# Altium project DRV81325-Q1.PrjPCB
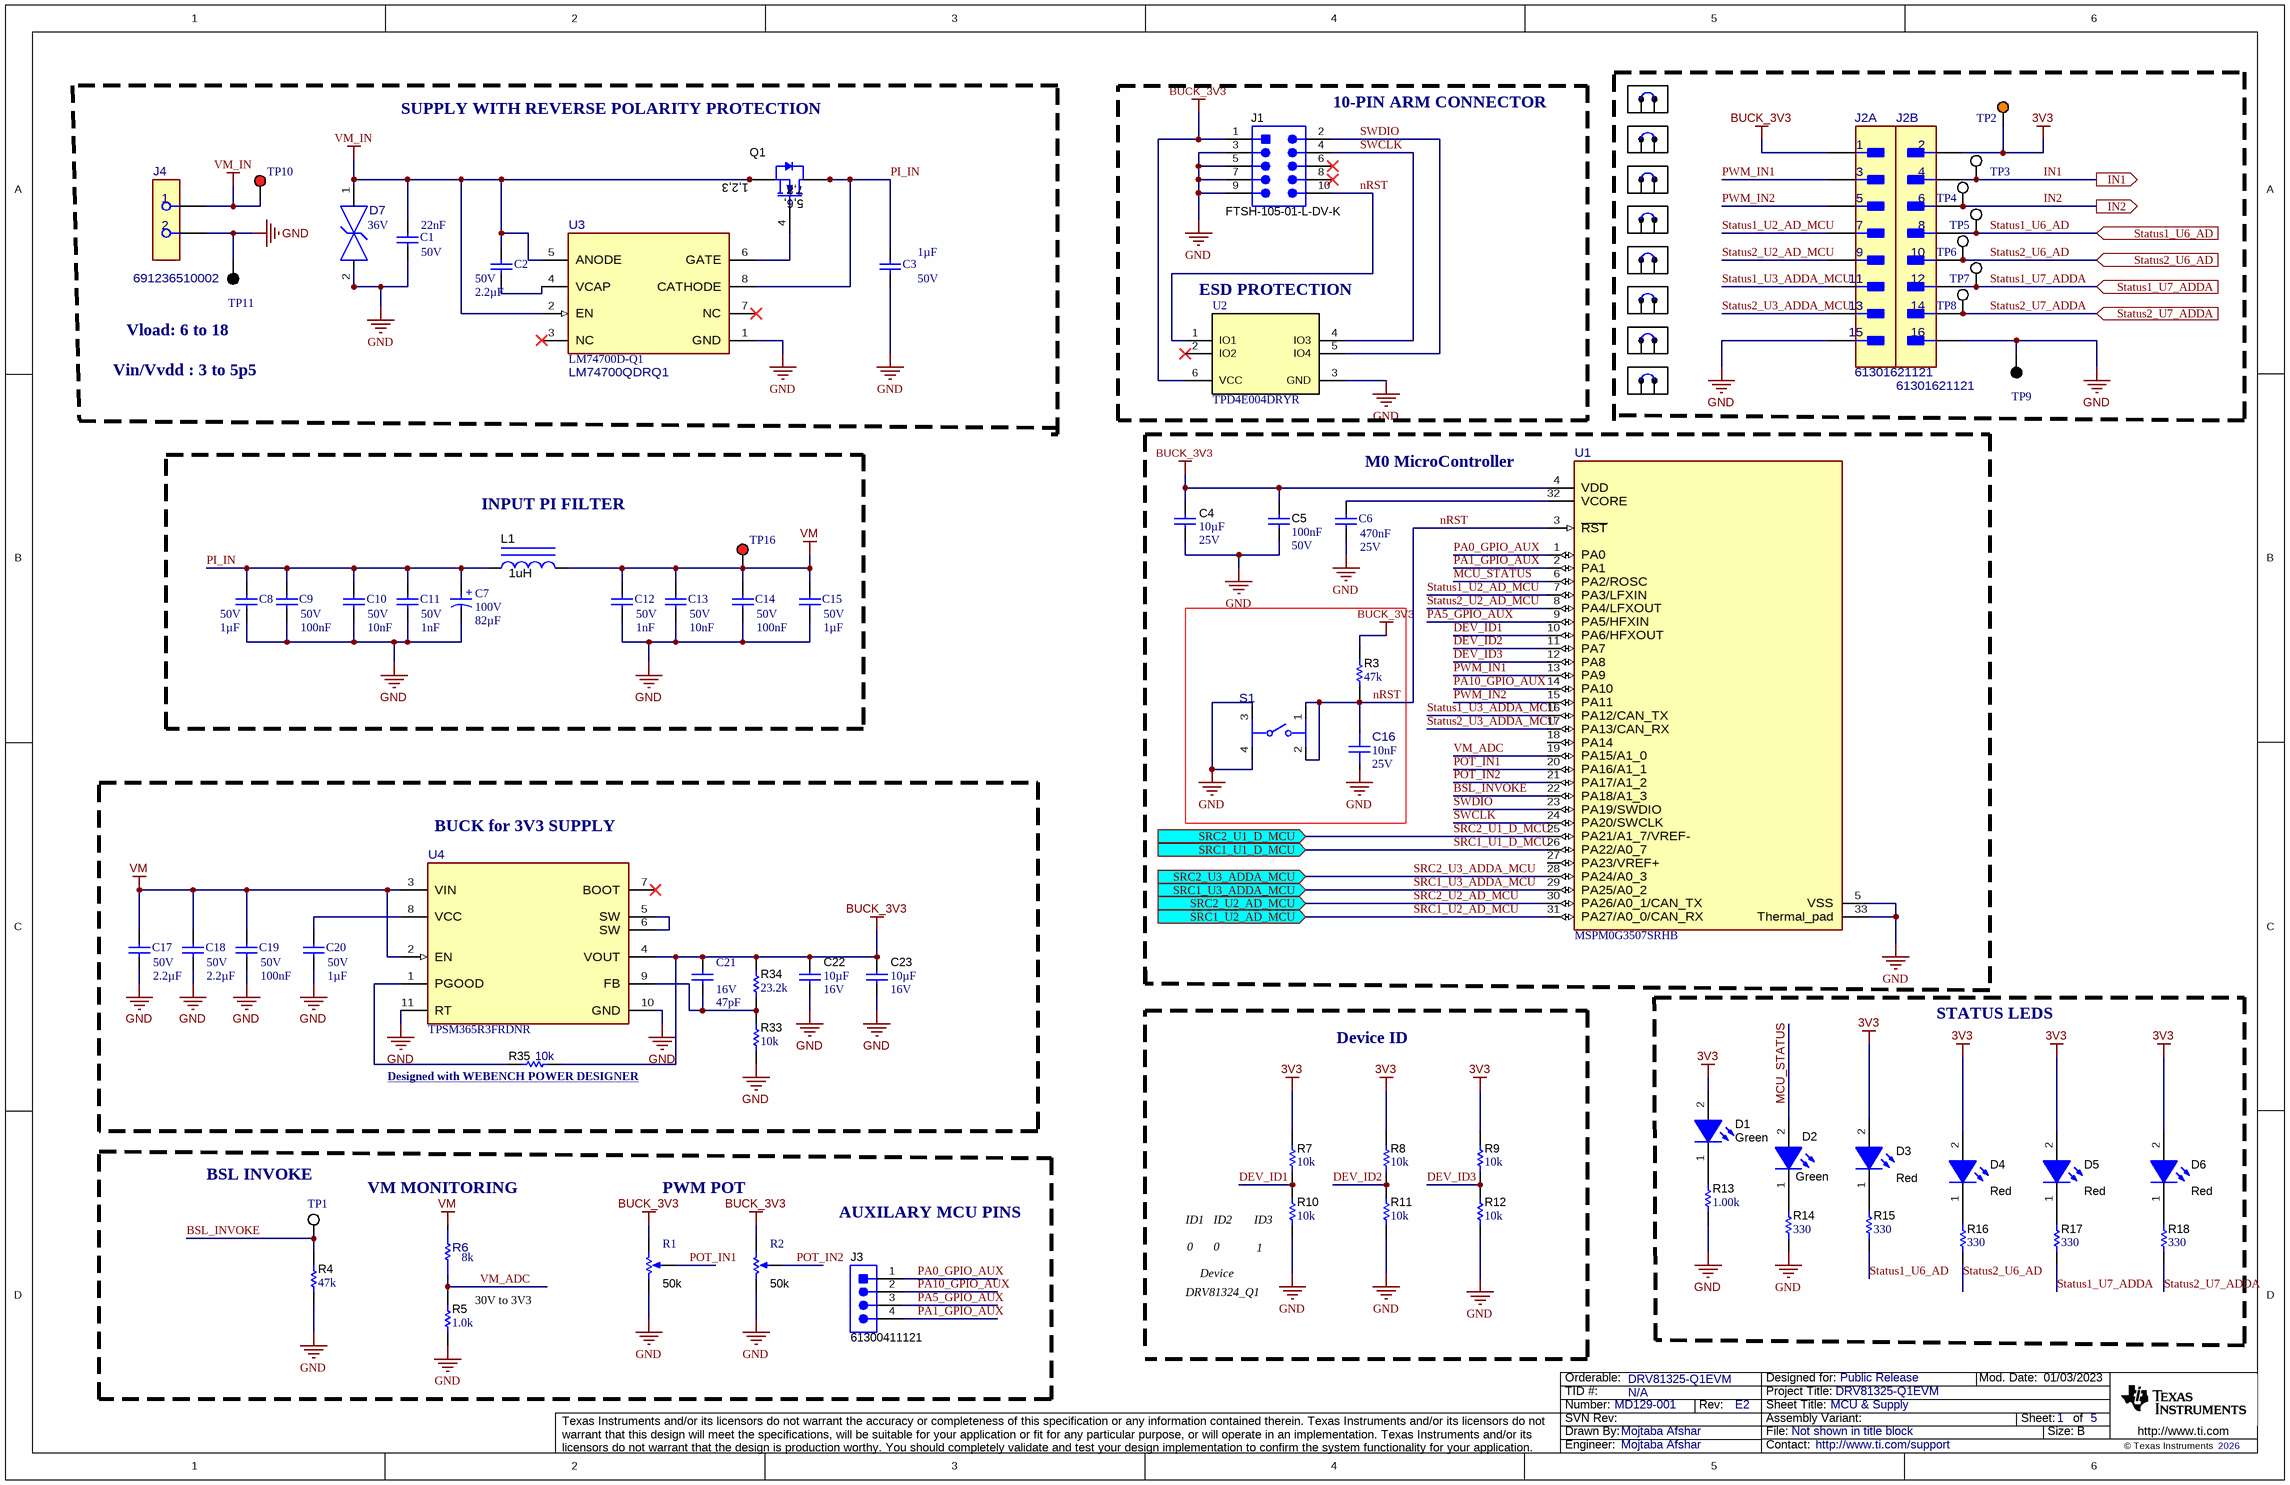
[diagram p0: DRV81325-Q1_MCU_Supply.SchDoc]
CopyrightYear: 2026; EVM_Orderable: DRV81325-Q1EVM; PCB_Layout: Mojtaba Afshar; PCB_Rev: E2; PRJ_Customer: Public Release; PRJ_Engineer: Mojtaba Afshar; PRJ_Number: MD129-001; PRJ_Title: DRV81325-Q1EVM; SCH_Rev: E2; TechSupport: http://www.ti.com/support; TID: N/A
5 sheets, 207 parts. Net scope: flat (ports and power ports of the same name join across sheets).
Board file: MD129_DRV81325_031026.PcbDoc
Sheets:
  DRV81325-Q1_MCU_Supply.SchDoc
  DRV81325-QD_IC.SchDoc
  DRV81325-QAD_IC.SchDoc
  DRV81325-QADDA_IC.SchDoc
  DRV81325-Q1_HW.SchDoc

## Sheet DRV81325-Q1_MCU_Supply.SchDoc: MCU & Supply
size 431 x 279 mm; Date: Not shown in title block; ApprovedBy: Not shown in title block; CheckedBy: Not shown in title block; Author: Not shown in title block; CompanyName: Not shown in title block; DrawnBy: Mojtaba Afshar; Engineer: Not shown in title block; Organization: Not shown in title block; Address1: Not shown in title block; Address2: Not shown in title block; Address3: Not shown in title block; Address4: Not shown in title block; DocumentNumber: 2; Revision: Use project parameter SCH_Rev; SheetNumber: 1; SheetTotal: 5; PageSetup: Record=PageOptions¦CenterHorizontal=True¦CenterVertical=True¦PrintScale=1.00¦XCorrection=1.00¦YCorrection=1.00¦PrintKind=0¦BorderSize=5000000¦LeftOffset=0¦BottomOffset=0¦Orientation=2¦PaperLength=1000¦PaperWidth=1000¦Scale=100¦PaperSource=15¦PrintQuality=600¦MediaType=1¦DitherType=10¦PaperKind=Letter¦PrintScaleMode=1

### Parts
C1  value 22nF  Rated Voltage (DC): 50V  [WCAP-CSGP_0603_L1.6W0.8H0.8_Reflow]  (hidden comment: 885012206091)
C2  value 2.2µF  Rated Voltage (DC): 50V  [WCAP-CSGP_1812_L4.5W3.2H2.5]  (hidden comment: 885012210032)
C3  value 1µF  Rated Voltage (DC): 50V  [WCAP-CSGP_1206_L3.2W1.6H1.6]  (hidden comment: 885012208093)
C4  Cap_F: 10µF  VDC_V: 25V  [0603]  (hidden comment: GRM188R61E106KA73D)
C5  Cap_F: 100nF  VDC_V: 50V  [0603]  (hidden comment: 885012206095)
C6  value 470nF  Rated Voltage (DC): 25V  [WCAP-CSGP_0603_L1.6W0.8H0.8_Reflow]  (hidden comment: 885012206075R)
C7  value 82µF  Rated Voltage (DC): 100V  [WCAP-ATUL_D10H20]  (hidden comment: 860040875004)
C8  value 1µF  Rated Voltage (DC): 50V  [WCAP-CSGP_1206_L3.2W1.6H1.6]  (hidden comment: 885012208093)
C9  value 100nF  Rated Voltage (DC): 50V  [WCAP-CSGP_0603_L1.6W0.8H0.8_Reflow]  (hidden comment: 885012206095)
C10  value 10nF  Rated Voltage (DC): 50V  [WCAP-CSGP_0402_L1W0.5H0.5]  (hidden comment: 885012205067)
C11  value 1nF  Rated Voltage (DC): 50V  [WCAP-CSGP_0402_L1W0.5H0.5]  (hidden comment: 885012205061)
C12  value 1nF  Rated Voltage (DC): 50V  [WCAP-CSGP_0402_L1W0.5H0.5]  (hidden comment: 885012205061)
C13  value 10nF  Rated Voltage (DC): 50V  [WCAP-CSGP_0402_L1W0.5H0.5]  (hidden comment: 885012205067)
C14  value 100nF  Rated Voltage (DC): 50V  [WCAP-CSGP_0603_L1.6W0.8H0.8_Reflow]  (hidden comment: 885012206095)
C15  value 1µF  Rated Voltage (DC): 50V  [WCAP-CSGP_1206_L3.2W1.6H1.6]  (hidden comment: 885012208093)
C16  Cap_F: 10nF  VDC_V: 25V  [FP-885012206065_0603-MFG]  (hidden comment: 885012206065)
C17  value 2.2µF  Rated Voltage (DC): 50V  [WCAP-CSGP_1812_L4.5W3.2H2.5]  (hidden comment: 885012210032)
C18  value 2.2µF  Rated Voltage (DC): 50V  [WCAP-CSGP_1812_L4.5W3.2H2.5]  (hidden comment: 885012210032)
C19  value 100nF  Rated Voltage (DC): 50V  [WCAP-CSGP_0603_L1.6W0.8H0.8_Reflow]  (hidden comment: 885012206095)
C20  value 1µF  Rated Voltage (DC): 50V  [WCAP-CSGP_1206_L3.2W1.6H1.6]  (hidden comment: 885012208093)
C21  value 47pF  Rated Voltage (DC): 16V  [WCAP-CSGP_0402_L1W0.5H0.5]  (hidden comment: 885012005029)
C22  VDC_V: 16V  ValueDisplayed: 10µF  [0805_150]  (hidden comment: 885012107014)
C23  VDC_V: 16V  ValueDisplayed: 10µF  [0805_150]  (hidden comment: 885012107014)
D1  value Green  [WL-SMCW_GREEN]  (hidden comment: 150060VS75000)
D2  value Green  [WL-SMCW_GREEN]  (hidden comment: 150060VS75000)
D3  value Red  [WL-SMCW_RED]  (hidden comment: 150060RS75000)
D4  value Red  [WL-SMCW_RED]  (hidden comment: 150060RS75000)
D5  value Red  [WL-SMCW_RED]  (hidden comment: 150060RS75000)
D6  value Red  [WL-SMCW_RED]  (hidden comment: 150060RS75000)
D7  VRWM: 36V  [FP-SMBJ36CA-13-F_SMB-MFG]  (hidden comment: SMBJ36CA-13-F)
J1  FTSH-105-01-L-DV-K  [Samtec_FTSH-105-01-x-DV-K]
J2  61301621121  [FP-61301621121_HDR16-MFG]  (parts A,B of 2)
J3  61300411121  [WURTH_61300411121]
J4  691236510002  [FP-691236510002_HHR2-MFG]
L1  ValueDisplayed: 1uH  [WE-HCC_1210]  (hidden comment: 7443320100)
Q1  CSD19502Q5B  [DNK0008A]  (value not drawn)
R1  value 50k  [Bourns_3352T]  (hidden comment: 3352T-1-503LF)
R2  value 50k  [Bourns_3352T]  (hidden comment: 3352T-1-503LF)
R3  ValueDisplayed: 47k  [0402]  (hidden comment: CRCW040247K0JNED)
R4  ValueDisplayed: 47k  [0402]  (hidden comment: CRCW040247K0JNED)
R5  ValueDisplayed: 1.0k  [0603]  (hidden comment: RC0603JR-071KL)
R6  value 8k  [FP-RT0603BRE078KL_0603-MFG]  (hidden comment: RT0603BRE078KL)
R7  ValueDisplayed: 10k  [0603L]  (hidden comment: RC0603JR-0710KL)
R8  ValueDisplayed: 10k  [0603L]  (hidden comment: RC0603JR-0710KL)
R9  ValueDisplayed: 10k  [0603L]  (hidden comment: RC0603JR-0710KL)
R10  ValueDisplayed: 10k  [0603L]  (hidden comment: RC0603JR-0710KL)
R11  ValueDisplayed: 10k  [0603L]  (hidden comment: RC0603JR-0710KL)
R12  ValueDisplayed: 10k  [0603L]  (hidden comment: RC0603JR-0710KL)
R13  ValueDisplayed: 1.00k  [0603]  (hidden comment: RC0603FR-071KL)
R14  ValueDisplayed: 330  [0603]  (hidden comment: RC0603JR-07330RL)
R15  ValueDisplayed: 330  [0603]  (hidden comment: RC0603JR-07330RL)
R16  ValueDisplayed: 330  [0603]  (hidden comment: RC0603JR-07330RL)
R17  ValueDisplayed: 330  [0603]  (hidden comment: RC0603JR-07330RL)
R18  ValueDisplayed: 330  [0603]  (hidden comment: RC0603JR-07330RL)
R33  ValueDisplayed: 10k  [0603L]  (hidden comment: RC0603JR-0710KL)
R34  ValueDisplayed: 23.2k  [0603]  (hidden comment: RC0603FR-0723K2L)
R35  ValueDisplayed: 10k  [0603L]  (hidden comment: RC0603JR-0710KL)
S1  430481025816  [FP-430481025816_SMT_SW_6MM2_6MM2-MFG]  (value not drawn)
SH1-J2-1  60900213421  [Wurth_60900213421]  (value not drawn)
SH2-J2  60900213421  [Wurth_60900213421]  (value not drawn)
SH3-J2  60900213421  [Wurth_60900213421]  (value not drawn)
SH4-J2  60900213421  [Wurth_60900213421]  (value not drawn)
SH5-J2  60900213421  [Wurth_60900213421]  (value not drawn)
SH6-J2  60900213421  [Wurth_60900213421]  (value not drawn)
SH7-J2  60900213421  [Wurth_60900213421]  (value not drawn)
SH8-J2  60900213421  [Wurth_60900213421]  (value not drawn)
TP1  5002  [Keystone5002]  (value not drawn)
TP2  5013  [Keystone5013]  (value not drawn)
TP3  5012  [Keystone5012]  (value not drawn)
TP4  5012  [Keystone5012]  (value not drawn)
TP5  5012  [Keystone5012]  (value not drawn)
TP6  5012  [Keystone5012]  (value not drawn)
TP7  5012  [Keystone5012]  (value not drawn)
TP8  5012  [Keystone5012]  (value not drawn)
TP9  5011  [Keystone5011]  (value not drawn)
TP10  5010  [Keystone5010]  (value not drawn)
TP11  5011  [Keystone5011]  (value not drawn)
TP16  5010  [Keystone5010]  (value not drawn)
U1  MSPM0G3507SRHB  [RHB0032E-MFG]
U2  TPD4E004DRYR  [DRY0006A]
U3  LM74700QDRQ1  PartNumber: LM74700D-Q1  [D0008A-MFG]
U4  TPSM365R3FRDNR  [RDN0011A-MFG]

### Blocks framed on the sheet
INPUT PI FILTER: C7-C15 L1 TP16
BUCK for 3V3 SUPPLY: C17-C23 R33-R35 U4
STATUS LEDS: D1-D6 R13-R18

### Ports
IN1 (out), IN2 (out), SRC1_U1_D_MCU (in), SRC1_U2_AD_MCU (in), SRC1_U3_ADDA_MCU (in), SRC2_U1_D_MCU (in), SRC2_U2_AD_MCU (in), SRC2_U3_ADDA_MCU (in), Status1_U6_AD (in), Status1_U7_ADDA (in), Status2_U6_AD (in), Status2_U7_ADDA (in)

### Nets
3V3: D1.2(A) D3.2(A) D4.2(A) D5.2(A) D6.2(A) J2.2 R7.1 R8.1 R9.1 TP2.1
BUCK_3V3: C4.1 C5.1 C21.2 C22.1 C23.1 J1.1 J2.1 R1.1(CCW) R2.1(CCW) R3.2 R34.2 R35.2 U1.4(VDD) U2.6(VCC) U4.4(VOUT)
GND: C1.1 C3.1 C4.2 C5.2 C6.1 C7.2(N) C8.1 C9.1 C10.1 C11.1 C12.1 C13.1 C14.1 C15.1 C16.2 C17.1 C18.1 C19.1 C20.1 C22.2 C23.2 D7.2 J1.3 J1.5 J1.7 J1.9 J2.15 J2.16 J4.2 R1.3(CW) R2.3(CW) R4.1 R5.1 R10.2 R11.2 R12.2 R13.1 R14.1 R33.1 S1.3 S1.4 TP9.1 TP11.1 U1.5(VSS) U1.33(Thermal_pad) U2.3(GND) U3.1(GND) U4.10(GND) U4.11(RT)
VM: C12.2 C13.2 C14.2 C15.2 C17.2 C18.2 C19.2 L1.2 R6.2 TP16.1 U4.2(EN) U4.3(VIN)
VM_IN: C1.2 C2.2 D7.1 J4.1 Q1.1(S) Q1.2(S) Q1.3(S) TP10.1 U3.2(EN) U3.5(ANODE)
BSL_INVOKE: R4.2 TP1.1 U1.22(PA18/A1_3)
DEV_ID1: R7.2 R10.1 U1.10(PA6/HFXOUT)
DEV_ID2: R8.2 R11.1 U1.11(PA7)
DEV_ID3: R9.2 R12.1 U1.12(PA8)
IN1: J2.4 TP3.1 ; port IN1
IN2: J2.6 TP4.1 ; port IN2
MCU_STATUS: D2.2(A) U1.6(PA2/ROSC)
nRST: C16.1 J1.10 R3.1 S1.1 S1.2 U1.3(~{RST}) U2.1(IO1)
PA0_GPIO_AUX: J3.1 U1.1(PA0)
PA1_GPIO_AUX: J3.4 U1.2(PA1)
PA5_GPIO_AUX: J3.3 U1.9(PA5/HFXIN)
PA10_GPIO_AUX: J3.2 U1.14(PA10)
PI_IN: C3.2 C7.1(P) C8.2 C9.2 C10.2 C11.2 L1.1 Q1.5(D) Q1.6(D) Q1.7(D) Q1.8(D) Q1.9(D) U3.8(CATHODE)
POT_IN1: R1.2(WIPER) U1.20(PA16/A1_1)
POT_IN2: R2.2(WIPER) U1.21(PA17/A1_2)
PWM_IN1: J2.3 U1.13(PA9)
PWM_IN2: J2.5 U1.15(PA11)
SRC1_U1_D_MCU: U1.26(PA22/A0_7) ; port SRC1_U1_D_MCU
SRC1_U2_AD_MCU: U1.31(PA27/A0_0/CAN_RX) ; port SRC1_U2_AD_MCU
SRC1_U3_ADDA_MCU: U1.29(PA25/A0_2) ; port SRC1_U3_ADDA_MCU
SRC2_U1_D_MCU: U1.25(PA21/A1_7/VREF-) ; port SRC2_U1_D_MCU
SRC2_U2_AD_MCU: U1.30(PA26/A0_1/CAN_TX) ; port SRC2_U2_AD_MCU
SRC2_U3_ADDA_MCU: U1.28(PA24/A0_3) ; port SRC2_U3_ADDA_MCU
Status1_U2_AD_MCU: J2.7 U1.7(PA3/LFXIN)
Status1_U3_ADDA_MCU: J2.11 U1.16(PA12/CAN_TX)
Status1_U6_AD: J2.8 R15.1 TP5.1 ; port Status1_U6_AD
Status1_U7_ADDA: J2.12 R17.1 TP7.1 ; port Status1_U7_ADDA
Status2_U2_AD_MCU: J2.9 U1.8(PA4/LFXOUT)
Status2_U3_ADDA_MCU: J2.13 U1.17(PA13/CAN_RX)
Status2_U6_AD: J2.10 R16.1 TP6.1 ; port Status2_U6_AD
Status2_U7_ADDA: J2.14 R18.1 TP8.1 ; port Status2_U7_ADDA
SWCLK: J1.4 U1.24(PA20/SWCLK) U2.4(IO3)
SWDIO: J1.2 U1.23(PA19/SWDIO) U2.5(IO4)
VM_ADC: R5.2 R6.1 U1.19(PA15/A1_0)
NetC2_1: C2.1 U3.4(VCAP)
NetC6_2: C6.2 U1.32(VCORE)
NetC20_2: C20.2 U4.8(VCC)
NetC21_1: C21.1 R33.2 R34.1 U4.9(FB)
NetD1_1: D1.1(K) R13.2
NetD2_1: D2.1(K) R14.2
NetD3_1: D3.1(K) R15.2
NetD4_1: D4.1(K) R16.2
NetD5_1: D5.1(K) R17.2
NetD6_1: D6.1(K) R18.2
NetQ1_4: Q1.4(G) U3.6(GATE)
NetR35_1: R35.1 U4.1(PGOOD)
NetU4_5: U4.5(SW) U4.6(SW)

Not connected (* = marked no-connect by the designer): J1 6* 8*; U1 18(PA14) 27(PA23/VREF+); U2 2(IO2)*; U3 3(NC)* 7(NC)*; U4 7(BOOT)*

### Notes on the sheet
- SUPPLY WITH REVERSE POLARITY PROTECTION
- (near J1) 10-PIN ARM CONNECTOR
- (near U2) ESD PROTECTION
- (near TP11) Vload: 6 to 18
- Vin/Vvdd : 3 to 5p5
- M0 MicroController
- Device ID
- (near R35) Designed with WEBENCH POWER DESIGNER <https://webench.ti.com/power-designer/switching-regulator/customize/4?VinMin=4.5&VinMax=65&O1V=3.3&O1I=0.3&base_pn=TPSM365R3F&AppType=None&Flavor=None&op_TA=30&origin=pf_panel&lang_chosen=en-US&optfactor=3&Topology=Buck&flavor=None&VoltageOption=None>
- (near TP1) BSL INVOKE
- (near R6) VM MONITORING
- PWM POT
- AUXILARY MCU PINS
- ID1
- ID2
- (near R10) ID3
- 30V to 3V3
- DRV81324_Q1
- 0
- Device
- (near R10) 1

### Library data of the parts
C1 = CMP-0119398-1: WCAP-CSGP Multilayer Ceramic Chip Capacitor, General Purpose, size 0603, X7R, 22nF, 50VDC; Manufacturer: Wurth Elektronik; Capacitance Tolerance: +/-10%; Case/Size Code: 0603; Dissipation Factor: 2.5%; Insulation Resistance: 10GOhm; Technical Reference: X7R0603223K050DFCT10000
C2 C17 C18 = CMP-0119739-1: WCAP-CSGP Multilayer Ceramic Chip Capacitor, General Purpose, size 1812, X7R, 2.2µF, 50VDC; Manufacturer: Wurth Elektronik; Capacitance Tolerance: +/-10%; Case/Size Code: 1812; Dissipation Factor: 2.5%; Insulation Resistance: 0.2GOhm; Technical Reference: X7R1812225K050DFCT10000
C3 C8 C15 C20 = CMP-0119636-1: WCAP-CSGP Multilayer Ceramic Chip Capacitor, General Purpose, size 1206, X7R, 1µF, 50VDC; Manufacturer: Wurth Elektronik; Capacitance Tolerance: +/-10%; Case/Size Code: 1206; Dissipation Factor: 3%; Insulation Resistance: 0.5GOhm; Technical Reference: X7R1206105K050DFCT10000
C4 = CMP-0860569-1: CAP, CERM, 10 µF, 25 V,+/- 10%, X5R, 0603; Manufacturer: MuRata; TaMin_C: -55°C; Polarized: N; SizeAreaWB_mm2: 4.68; U/M: EA; Value: 10uF; TaMax_C: 85°C; SizeZ_mm: 1; SizeX_mm: 1.6; SizeY_mm: 0.8; SizeArea_mm2: 1.28; AEC Category: Q200
C5 = CMP-0006837-4: CAP, CERM, 0.1 uF, 50 V, +/- 10%, X7R, 0603; Manufacturer: Wurth Elektronik; TaMin_C: -55°C; Polarized: N; SizeAreaWB_mm2: 4.68; Value1: Unknown; U/M: EA; Value: 0.1uF; TaMax_C: 125°C; SizeZ_mm: 1; SizeX_mm: 1.6; SizeY_mm: 0.8; SizeArea_mm2: 1.28; AEC Category: Q200
C6 = CMP-0119380-1: WCAP-CSGP Multilayer Ceramic Chip Capacitor, General Purpose, size 0603, X7R Class II, 470nF, 25VDC; Manufacturer: Wurth Elektronik; Capacitance Tolerance: +/-10%; Case/Size Code: 0603; Dissipation Factor: 10%; Insulation Resistance: 1.1GOhm; Technical Reference: X7R0603474K025DFCT20000
C7 = CMP-0102582-1: WCAP-ATUL Aluminum Electrolytic Capacitor, Radial, THT, D10 x H20mm, 82µF, 100V; Manufacturer: Wurth Elektronik; Capacitance Tolerance: 20%; Dissipation Factor: 9%; Endurance: 7000h; Leakage Current: 82uA; Ripple Current: 600mA; Technical Reference: ATDF200820M100DSPAAG000
C9 C14 C19 = CMP-0119402-1: WCAP-CSGP Multilayer Ceramic Chip Capacitor, General Purpose, size 0603, X7R, 100nF, 50VDC; Manufacturer: Wurth Elektronik; Capacitance Tolerance: +/-10%; Case/Size Code: 0603; Dissipation Factor: 3%; Insulation Resistance: 5GOhm; Technical Reference: X7R0603104K050DFCT10000
C10 C13 = CMP-0119297-1: WCAP-CSGP Multilayer Ceramic Chip Capacitor, General Purpose, size 0402, X7R, 10nF, 50VDC; Manufacturer: Wurth Elektronik; Capacitance Tolerance: +/-10%; Case/Size Code: 0402; Dissipation Factor: 2.5%; Insulation Resistance: 10GOhm; Technical Reference: X7R0402103K050DFCT10000
C11 C12 = CMP-0119291-1: WCAP-CSGP Multilayer Ceramic Chip Capacitor, General Purpose, size 0402, X7R, 1nF, 50VDC; Manufacturer: Wurth Elektronik; Capacitance Tolerance: +/-10%; Case/Size Code: 0402; Dissipation Factor: 2.5%; Insulation Resistance: 10GOhm; Technical Reference: X7R0402102K050DFCT10000
C16 = CMP-0120893-1: 10000 pF ±10% 25V Ceramic Capacitor X7R 0603 (1608 Metric); Manufacturer: Wurth Electronics; AEC Qualified: No; SizeZ_mm: 0.87mm; TempCo: 15%; Value: 10nF
C21 = CMP-0050226-1: WCAP-CSGP Multilayer Ceramic Chip Capacitor, General Purpose, size 0402, NP0, 47pF, 16VDC; Manufacturer: Wurth Elektronik; Capacitance Tolerance: +/-5%; Insulation Resistance: 10GOhm; Q Factor: 1000; Technical Reference: NP00402470J016DFCT10000; Case/Size Code: 0402
C22 C23 = CMP-0078154-1: CAP, CERM, 10 µF, 16 V,+/- 20%, X5R, 0805; Manufacturer: Wurth Elektronik; TaMin_C: -55°C; Polarized: N; SizeAreaWB_mm2: 6.75; U/M: EA; Value: 10uF; TaMax_C: 85°C; SizeZ_mm: 1.5; SizeX_mm: 2; SizeY_mm: 1.25; Cap_Case: 0805; SizeArea_mm2: 2.5; AEC Category: Q200
D1 D2 = CMP-0002894-2: LED, Green, SMD; Manufacturer: Wurth Elektronik; Type: AlInGaP; Value2: 2V; Io_A: 20mA; Value1: W
D3-D6 = CMP-0002947-3: LED, Red, SMD; Manufacturer: Wurth Elektronik; Value1: 0.072W; Vf_V: 2V; Angle: 140; Tjmax_C: 85°C; Type: AlInGaP; Vr_V: 5V; Io_A: 30mA; Power_TotalModule: 72mW
D7 = CMP-0098087-1: 58.1V Clamp 10.3A Ipp Tvs Diode Surface Mount SMB; Manufacturer: Diodes Inc; AEC Qualified: No; Standoff Height: 0.05mm; TJmax_C: +150°C; Direction: Bidirectional; Breakdown Voltage: 40V; SizeZ_mm: 2.5mm; Ppk: 600W; Number Of Channels: 1
J1 = CMP-0075634-2: Header(Shrouded), 1.27mm, 5x2, Gold, SMT; Manufacturer: Samtec; Pitch_mm: 1.27; Gender: Male; Cert_CSA: Y; Current_A: 3.3A; Row_Count: 2
J2 = CMP-0125672-1: Connector Header Through Hole 16 position 0.100" (2.54mm); Manufacturer: Wurth; ContactFinish: Gold; Current_A: 3A; Row_Count: 2; Voltage_V: 250V; AEC Qualified: No; Conn Gender: Male; Conn Orientation: Straight; SizeZ_mm: 8.89mm
J3 = CMP-0054798-2: Header, 2.54 mm, 4x1, Gold, TH; Manufacturer: Wurth Elektronik; Pitch_mm: 2.54; Gender: Male; Row_Count: 1; Cert_UL: Y; Shrouded: N
J4 = CMP-0121282-1: 2 Position Wire to Board Terminal Block Horizontal with Board 0.200" (5.08mm) Through Hole; Manufacturer: Wurth Electronics; Current_A: 20A; Row_Count: 1; Voltage_V: 300V; AEC Qualified: No; Conn Gender: Female; Is Female: yes; Max Wire Gauge: 12; Min Wire Gauge: 30; SizeZ_mm: 18.1mm
L1 = CMP-0063986-1: Inductor, Shielded Drum Core, Ferrite, 1 uH, 24 A, 0.0012 ohm, SMD; Manufacturer: Wurth Elektronik; Isat: 32A @ 30% inductance drop; Irms: 24A @ 50C rise; Green_Lifecycle: Active; SizeAreaWB_mm2: 188.94; DCR_ohm: 1.2m; Green_REACh: Passed; Value: 1uH; Imax_A: 24A; SizeZ_mm: 10; SizeX_mm: 12.1; SizeY_mm: 11.4; SizeArea_mm2: 137.94; Ind_H: 1µH; AEC Category: Q200
Q1 = CMP-0000915-2: MOSFET, N-CH, 80 V, 100 A, DNK0008A (VSON-CLIP-8); Alternate Manufacturer: None; Manufacturer: Texas Instruments; SizeZ_mm: 1; ChType: N; Value2: 48 nC; VdsMax_V: 80V; SizeX_mm: 6; SizeY_mm: 5; Vgs_V: 20V; Value: 80V; SizeArea_mm2: 30; AEC Category: Q101; IdsMax_A: 100A; SizeAreaWB_mm2: 56; U/M: EA; QgTyp_nC: 48
R1 R2 = CMP-0001777-2: Trimming Potentiometer, 50K, 0.5W, TH; Manufacturer: Bourns; CompType: Trimmer
R3 R4 = CMP-0026935-3: RES, 47 k, 5%, 0.063 W, AEC-Q200 Grade 0, 0402; Manufacturer: Vishay-Dale; Power_W: 63mW; TempCo: 200 ppm/C; Value_Code: 47k0; Value: 47k; EIA_Code: E24; SizeX_mm: 1; SizeY_mm: 0.5; SizeZ_mm: 0.6; Value2: 0.063W; AEC Qualified: Y; VDC_V: 50V; AEC Category: Q200; AEC Grade: 0
R5 = CMP-0025899-5: RES, 1.0 k, 5%, 0.1 W, 0603; Manufacturer: Yageo; Power_W: 100mW; TempCo: 100 ppm/C; Value_Code: 1k00; Value: 1.0k; EIA_Code: E24; Res_ohm: 1k; SizeX_mm: 1.6; SizeY_mm: 0.8; SizeZ_mm: 1; Value2: 0.1W; SizeArea_mm2: 1.28; AEC Qualified: N; VDC_V: 75V; AEC Category: Q200; SizeAreaWB_mm2: 4.68
R6 = CMP-0122747-1: 8 kOhms ±0.1% 0.1W, 1/10W Chip Resistor 0603 (1608 Metric) Thin Film; Manufacturer: Yageo; AEC Qualified: No; Power_W: 100mW; SizeZ_mm: 0.55mm; TempCo: 50ppm/°C; VDC_V: 75V
R7-R12 R33 = CMP-0025886-5: RES, 10 k, 5%, 0.1 W, 0603; Manufacturer: Yageo; Power_W: 100mW; TempCo: 100 ppm/C; Value_Code: 10k0; Value: 10k; EIA_Code: E24; SizeX_mm: 1.6; SizeY_mm: 0.8; SizeZ_mm: 1; Value2: 0.1W; SizeArea_mm2: 1.28; AEC Qualified: N; VDC_V: 75V; AEC Category: Q200; SizeAreaWB_mm2: 4.68
R13 = CMP-0022895-5: RES, 1.00 k, 1%, 0.1 W, 0603; Manufacturer: Yageo; Power_W: 100mW; TempCo: 100 ppm/C; Value_Code: 1k00; Value: 1.00k; EIA_Code: E96; Res_ohm: 1k; SizeX_mm: 1.6; SizeY_mm: 0.8; SizeZ_mm: 1; Value2: 0.1W; SizeArea_mm2: 1.28; AEC Qualified: N; VDC_V: 75V; AEC Category: Q200; SizeAreaWB_mm2: 4.68
R14-R18 = CMP-0025912-5: RES, 330, 5%, 0.1 W, 0603; Manufacturer: Yageo; Power_W: 100mW; TempCo: 100 ppm/C; Value_Code: 330R; Value: 330; EIA_Code: E24; SizeX_mm: 1.6; SizeY_mm: 0.8; SizeZ_mm: 1; Value2: 0.1W; SizeArea_mm2: 1.28; AEC Qualified: N; VDC_V: 75V; AEC Category: Q200; SizeAreaWB_mm2: 4.68
R34 = CMP-0022933-5: RES, 23.2 k, 1%, 0.1 W, 0603; Manufacturer: Yageo; Power_W: 100mW; TempCo: 100 ppm/C; Value_Code: 23k2; Value: 23.2k; EIA_Code: E96; SizeX_mm: 1.6; SizeY_mm: 0.8; SizeZ_mm: 1; Value2: 0.1W; SizeArea_mm2: 1.28; AEC Qualified: N; VDC_V: 75V; AEC Category: Q200; SizeAreaWB_mm2: 4.68
R35 = CMP-0025886-3: RES, 10 k, 5%, 0.1 W, 0603; Manufacturer: Yageo; Power_W: 100mW; TempCo: 100 ppm/C; Value_Code: 10k0; U/M: EA; Value: 10k; EIA_Code: E24; SizeX_mm: 1.6; SizeY_mm: 0.8; SizeZ_mm: 1; Value2: 0.1W; SizeArea_mm2: 1.28; VDC_V: 50V; AEC Category: Q200
S1 = CMP-0097347-1: Tactile Switch SPST-NO Top Actuated Surface Mount; Manufacturer: Wurth Electronics; VDC_V: 12V; Electromechanical Life: 1000000Cycles; SizeZ_mm: 2.7mm; Coil Resistance_ohm: 100mΩ; Operating Force: 160gf; AEC Qualified: No; Contact Current Rating: 50mA
SH1-J2-1 SH2-J2 SH3-J2 SH4-J2 SH5-J2 SH6-J2 SH7-J2 SH8-J2 = CMP-0003761-2: Shunt, 2.54mm, Gold, Black; Manufacturer: Wurth Elektronik
TP1 = CMP-0055139-2: Test Point, Miniature, White, TH; Manufacturer: Keystone Electronics; ContactFinish: Silver; Green_REACh: Passed; CT: TRUE; Green_Lifecycle: Active; CNHeader: FALSE
TP2 = CMP-0055150-1: Test Point, Multipurpose, Orange, TH; Manufacturer: Keystone; CNHeader: FALSE; Green_Lifecycle: Active; Green_REACh: Passed; ContactFinish: Silver; CT: TRUE
TP3-TP8 = CMP-0055149-2: Test Point, Multipurpose, White, TH; Manufacturer: Keystone Electronics; ContactFinish: Silver; CT: TRUE; CNHeader: FALSE; Green_Lifecycle: Active; Green_REACh: Passed
TP9 = CMP-0055148-2: Test Point, Multipurpose, Black, TH; Manufacturer: Keystone Electronics; CNHeader: FALSE; ContactFinish: Silver; Green_REACh: Passed; Green_Lifecycle: Active; CT: TRUE
TP10 TP16 = CMP-0055147-2: Test Point, Multipurpose, Red, TH; Manufacturer: Keystone Electronics; CNHeader: FALSE; Green_Lifecycle: Active; Green_REACh: Passed; ContactFinish: Silver; CT: TRUE
TP11 = CMP-0055148-2: Test Point, Multipurpose, Black, TH; Manufacturer: Keystone Electronics; CNHeader: FALSE; Green_Lifecycle: Active; Green_REACh: Passed; ContactFinish: Silver; CT: TRUE
U1 = CMP-0093963-1: Mixed-Signal Microcontrollers with CAN-FD Interface, VQFN32; Manufacturer: Texas Instruments; TaMin_C: -40°C; Interface: I2C,SPI,UART,CAN,LIN,IrDA,SMBus; Number Of Cores: 1; Number Of Pwm Channels: 16; Data Bus Width: 32bits; Frequency_Fixed: 80MHz; Core Architecture: ARM Cortex-M0+; Number Of Timers/Counters: 7; Number Of Adc Channels: 10; Number Of Uart Channels: 4; Standoff Height: 0mm; Ram Size: 32KBytes; Number Of A/D Converters: 2; SizeZ_mm: 1mm; AEC Qualified: No; TaMax_C: +125°C; Memory Size: 128KBytes; TJmax_C: +130°C; Min Supply Voltage: 1.62V; Max Supply Voltage: 3.6V; Memory Type: FLASH; Number Of I/Os: 28
U2 = CMP-0043115-2: ESD-Protection Array for High-Speed Data Interfaces, 4 Channels, -40 to +85 degC, 6-pin SON (DRY), Green (RoHS & no Sb/Br); Manufacturer: Texas Instruments; IO Leakage Current(nA): 1; USB High Speed: TRUE; IO Capacitance(Typ)(pF): 1.6; SubFamily: ESD Solution; IEC 61000-4-2 Contact(+/- kV): 8; Breakdown Voltage(Min)(V): 6; IEC 61000-4-2 Air-Gap(+/- kV): 12; AEC Category: Q200; AEC Qualified: N; CompType: IC; SizeAreaWB_mm2: 4.9; SizeArea_mm2: 1.45; SizeX_mm: 1.0; SizeZ_mm: 0.6
U3 = CMP-0125797-1: Manufacturer: Texas Instruments; SizeZ_mm: 1.75mm; Standoff Height: 0.11mm
U4 = CMP-0094617-1: 3-V to 65-V Input, 1-V to 13-V Output, 600-mA Synchronous Buck Converter Power Module in a HotRod QFN Package; Manufacturer: Texas Instruments; SizeZ_mm: 2.1mm; AEC Qualified: No; Max Duty Cycle: 98%; Max Supply Voltage: 65V; Min Supply Voltage: 3.6V; Nominal Supply Current: 17-18uA; Number Of Outputs: 1; Output Type: AdjustableProgrammable; Output Voltage: 1-13V; Standoff Height: 0mm; Switching Frequency: 200-2200kHz; TJmax_C: +125°C

## Sheet DRV81325-QD_IC.SchDoc: MSPM0G3507-Q1
size 431 x 279 mm; Date: Not shown in title block; ApprovedBy: Not shown in title block; CheckedBy: Not shown in title block; Author: Not shown in title block; CompanyName: Not shown in title block; DrawnBy: Mojtaba Afshar; Engineer: Not shown in title block; Organization: Not shown in title block; Address1: Not shown in title block; Address2: Not shown in title block; Address3: Not shown in title block; Address4: Not shown in title block; DocumentNumber: 1; Revision: Use project parameter SCH_Rev; SheetNumber: 2; SheetTotal: 5; PageSetup: Record=PageOptions¦CenterHorizontal=True¦CenterVertical=True¦PrintScale=1.00¦XCorrection=1.00¦YCorrection=1.00¦PrintKind=0¦BorderSize=5000000¦LeftOffset=0¦BottomOffset=0¦Orientation=2¦PaperLength=1000¦PaperWidth=1000¦Scale=100¦PaperSource=15¦PrintQuality=600¦MediaType=1¦DitherType=10¦PaperKind=Letter¦PrintScaleMode=1
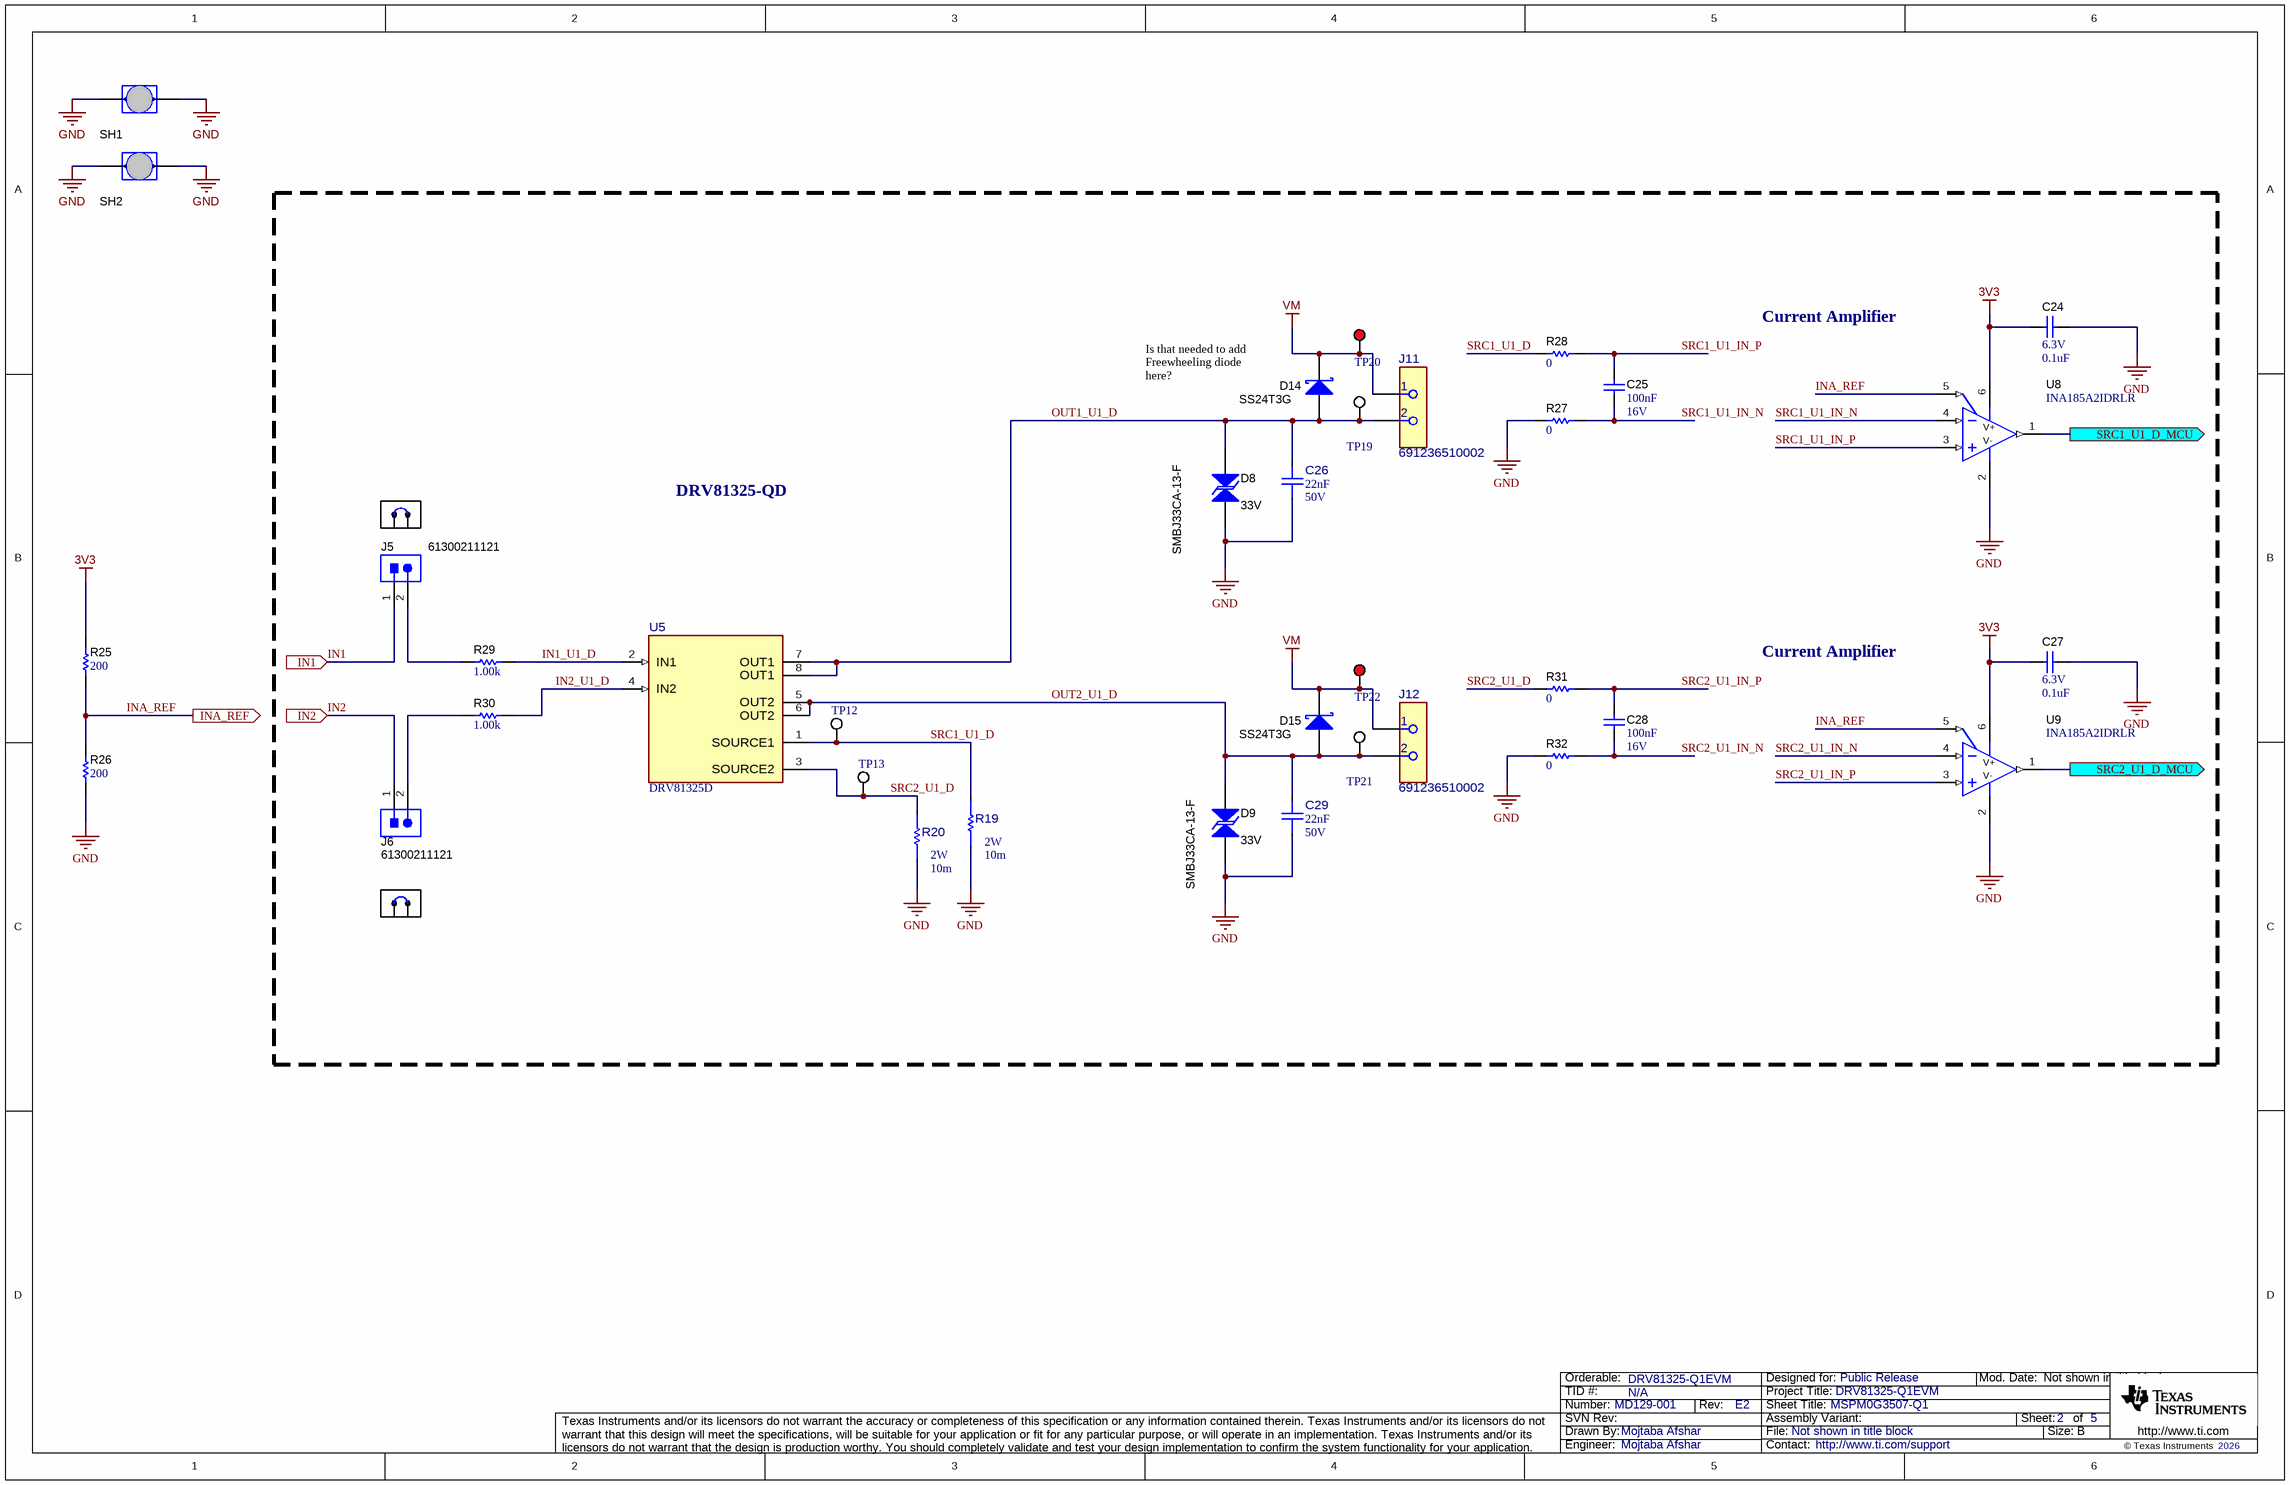
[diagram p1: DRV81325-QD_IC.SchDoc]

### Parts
C24  VDC_V: 6.3V  ValueDisplayed: 0.1uF  [0402]  (hidden comment: 885012105001)
C25  Cap_F: 100nF  VDC_V: 16V  [0603]  (hidden comment: 885012206046)
C26  Cap_F: 22nF  VDC_V: 50V  [FP-885012206091_0603-MFG]  (hidden comment: 885012206091)
C27  VDC_V: 6.3V  ValueDisplayed: 0.1uF  [0402]  (hidden comment: 885012105001)
C28  Cap_F: 100nF  VDC_V: 16V  [0603]  (hidden comment: 885012206046)
C29  Cap_F: 22nF  VDC_V: 50V  [FP-885012206091_0603-MFG]  (hidden comment: 885012206091)
D8  SMBJ33CA-13-F  value 33V  [SMB-Bi]
D9  SMBJ33CA-13-F  value 33V  [SMB-Bi]
D14  SS24T3G  [SMB]
D15  SS24T3G  [SMB]
J5  61300211121  [WURTH_61300211121]
J6  61300211121  [WURTH_61300211121]
J11  691236510002  [FP-691236510002_HHR2-MFG]
J12  691236510002  [FP-691236510002_HHR2-MFG]
R19  Res_ohm: 10m  Power_W: 2W  [FP-PCS2512DR0100ET_2512-MFG]  (hidden comment: PCS2512DR0100ET)
R20  Res_ohm: 10m  Power_W: 2W  [FP-PCS2512DR0100ET_2512-MFG]  (hidden comment: PCS2512DR0100ET)
R25  ValueDisplayed: 200  [0603]  (hidden comment: RC0603FR-07200RL)
R26  ValueDisplayed: 200  [0603]  (hidden comment: RC0603FR-07200RL)
R27  ValueDisplayed: 0  [0603]  (hidden comment: ERJ-3GEY0R00V)
R28  ValueDisplayed: 0  [0603]  (hidden comment: ERJ-3GEY0R00V)
R29  ValueDisplayed: 1.00k  [0603]  (hidden comment: RC0603FR-071KL)
R30  ValueDisplayed: 1.00k  [0603]  (hidden comment: RC0603FR-071KL)
R31  ValueDisplayed: 0  [0603]  (hidden comment: ERJ-3GEY0R00V)
R32  ValueDisplayed: 0  [0603]  (hidden comment: ERJ-3GEY0R00V)
SH1  Jumper_2p  [Harwin_D3082-05]  (value not drawn)
SH2  Jumper_2p  [Harwin_D3082-05]  (value not drawn)
SH-J5  60900213421  [Wurth_60900213421]  (value not drawn)
SH-J6  60900213421  [Wurth_60900213421]  (value not drawn)
TP12  5002  [Keystone5002]  (value not drawn)
TP13  5002  [Keystone5002]  (value not drawn)
TP19  5012  [Keystone5012]  (value not drawn)
TP20  5010  [Keystone5010]  (value not drawn)
TP21  5012  [Keystone5012]  (value not drawn)
TP22  5010  [Keystone5010]  (value not drawn)
U5  DRV81325D  [D0008A-MFG]
U8  INA185A2IDRLR  [DRL0006A]
U9  INA185A2IDRLR  [DRL0006A]

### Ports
IN1 (in), IN2 (in), INA_REF (out), SRC1_U1_D_MCU (out), SRC2_U1_D_MCU (out)

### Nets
3V3: C24.2 C27.2 R25.2 U8.6(V+) U9.6(V+)
GND: C24.1 C26.1 C27.1 C29.1 D8.1 D9.1 R19.1 R20.1 R26.1 R27.1 R32.1 SH1.1 SH1.2 SH2.1 SH2.2 U8.2(V-) U9.2(V-)
VM: D14.1(K) D15.1(K) J11.1 J12.1 TP20.1 TP22.1
IN1: J5.1 ; port IN1
IN1_U1_D: R29.2 U5.2(IN1)
IN2: J6.1 ; port IN2
IN2_U1_D: R30.2 U5.4(IN2)
INA_REF: R25.1 R26.2 U8.5(REF) U9.5(REF) ; port INA_REF
OUT1_U1_D: C26.2 D8.2 D14.2(A) J11.2 TP19.1 U5.7(OUT1) U5.8(OUT1)
OUT2_U1_D: C29.2 D9.2 D15.2(A) J12.2 TP21.1 U5.5(OUT2) U5.6(OUT2)
SRC1_U1_D: R19.2 R28.1 TP12.1 U5.1(SOURCE1)
SRC1_U1_D_MCU: U8.1(OUT) ; port SRC1_U1_D_MCU
SRC1_U1_IN_N: C25.2 R27.2 U8.4(IN-)
SRC1_U1_IN_P: C25.1 R28.2 U8.3(IN+)
SRC2_U1_D: R20.2 R31.1 TP13.1 U5.3(SOURCE2)
SRC2_U1_D_MCU: U9.1(OUT) ; port SRC2_U1_D_MCU
SRC2_U1_IN_N: C28.2 R32.2 U9.4(IN-)
SRC2_U1_IN_P: C28.1 R31.2 U9.3(IN+)
NetJ5_2: J5.2 R29.1
NetJ6_2: J6.2 R30.1

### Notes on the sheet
- Current Amplifier
- Is that needed to add Freewheeling diode here?
- DRV81325-QD

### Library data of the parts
C24 C27 = CMP-0006219-2: CAP, CERM, 0.1 uF, 6.3 V, +/- 20%, X5R, 0402; Manufacturer: Wurth Elektronik; TaMin_C: -55°C; Polarized: N; SizeAreaWB_mm2: 3; Value1: Unknown; U/M: EA; Value: 0.1uF; TaMax_C: 85°C; SizeZ_mm: 0.6; SizeX_mm: 1; SizeY_mm: 0.5; Cap_F: 100nF; AEC Category: Q200
C25 C28 = CMP-0006829-4: CAP, CERM, 0.1 uF, 16 V, +/- 10%, X7R, 0603; Manufacturer: Wurth Elektronik; TaMin_C: -55°C; Polarized: N; SizeAreaWB_mm2: 4.68; Value1: Unknown; U/M: EA; Value: 0.1uF; TaMax_C: 125°C; SizeZ_mm: 1; SizeX_mm: 1.6; SizeY_mm: 0.8; SizeArea_mm2: 1.28; AEC Category: Q200
C26 C29 = CMP-0120895-1: 0.022 µF ±10% 50V Ceramic Capacitor X7R 0603 (1608 Metric); Manufacturer: Wurth Electronics; AEC Qualified: No; SizeZ_mm: 0.87mm; TempCo: 15%; Value: 22nF
D8 D9 = CMP-0005564-3: Diode, TVS, Bi, 33 V, SMB; Manufacturer: Diodes Inc.; SizeX_mm: 5.6; Ppk: 600W; SizeAreaWB_mm2: 44.156; SizeZ_mm: 2.6; SizeArea_mm2: 21.336; SizeY_mm: 3.81; AEC Category: Q101
D14 D15 = CMP-0028778-2: Diode, Schottky, 40 V, 2 A, AEC-Q101, SMB; Manufacturer: ON Semiconductor; AEC Qualified: Y; Value: 40V; TJmax_C: 150°C; Value1: 2A; Green_Lifecycle: Active; Value2: 0.5V; SizeX_mm: 5.6; SizeAreaWB_mm2: 44.156; SizeY_mm: 3.81; SizeArea_mm2: 21.336; Green_REACh: Passed; SizeZ_mm: 2.6; AEC Category: Q101; Vf_V: 500mV
J5 J6 = CMP-0054794-2: Header, 2.54 mm, 2x1, Gold, TH; Manufacturer: Wurth Elektronik; Shrouded: N; Gender: Male; Green_REACh: Passed; Pitch_mm: 2.54; Green_Lifecycle: Active; Row_Count: 1; Cert_UL: Y
J11 J12 = CMP-0121282-1: as J4 on sheet DRV81325-Q1_MCU_Supply
R19 R20 = CMP-0088493-1: 10 mOhms ±0.5% 2W Chip Resistor 2512 (6432 Metric) Automotive AEC-Q200, Current Sense, Moisture Resistant Metal Film; Manufacturer: Ohmite; SizeZ_mm: 0.664mm; AEC Grade: Grade 0; TempCo: 50ppm/°C; AEC Qualified: Yes; Tolerance_%: 0%
R25 R26 = CMP-0022902-5: RES, 200, 1%, 0.1 W, 0603; Manufacturer: Yageo; Power_W: 100mW; TempCo: 100 ppm/C; Value_Code: 200R; Value: 200; EIA_Code: E96; SizeX_mm: 1.6; SizeY_mm: 0.8; SizeZ_mm: 1; Value2: 0.1W; SizeArea_mm2: 1.28; AEC Qualified: N; VDC_V: 75V; AEC Category: Q200; SizeAreaWB_mm2: 4.68
R27 R28 R31 R32 = CMP-0025874-4: RES, 0, 5%, 0.1 W, AEC-Q200 Grade 0, 0603; Manufacturer: Panasonic; Power_W: 100mW; TempCo: 600 ppm/C; Value_Code: 0000; Value: 0; EIA_Code: E24; SizeX_mm: 1.6; SizeY_mm: 0.8; SizeZ_mm: 1; Value2: 0.1W; SizeArea_mm2: 1.28; AEC Qualified: Y; VDC_V: 50V; AEC Category: Q200; SizeAreaWB_mm2: 4.68
R29 R30 = CMP-0022895-5: as R13 on sheet DRV81325-Q1_MCU_Supply
SH1 SH2 = CMP-0075110-1: 1mm Uninsulated Shorting Plug, 10.16mm spacing, TH; PartNumber: D3082-05; Manufacturer: Harwin; CNHeader: False; CompType: Jumper Wire; Green_Lifecycle: Active; Green_REACh: Passed
SH-J5 SH-J6 = CMP-0003761-2: as SH1-J2-1 on sheet DRV81325-Q1_MCU_Supply
TP12 TP13 = CMP-0055139-2: as TP1 on sheet DRV81325-Q1_MCU_Supply
TP19 TP21 = CMP-0055149-2: as TP3 on sheet DRV81325-Q1_MCU_Supply
TP20 TP22 = CMP-0055147-2: Test Point, Multipurpose, Red, TH; Manufacturer: Keystone Electronics; CT: TRUE; ContactFinish: Silver; Green_Lifecycle: Active; CNHeader: FALSE; Green_REACh: Passed
U5 = CMP-0127644-1: Dual Channel Protected Low side switch, SOIC8; Manufacturer: Texas Instruments; SizeZ_mm: 1.75mm; AEC Qualified: Yes; AEC Grade: Grade 1; Max Supply Voltage: 5.5V; Min Supply Voltage: 3V; Number Of Outputs: 2; Standoff Height: 0.11mm; TaMax_C: +125°C; TaMin_C: -40°C; TJmax_C: +150°C
U8 U9 = CMP-0085242-1: Bidirectional, Precision Low- and High-Side Voltage Output, Current-Sense Amplifier, DRL0006A (SOT-5X3-6); Alternate PartNumber: INA185A2IDRLT; Alternate Manufacturer: Texas Instruments; SizeY_mm: 1.6; SizeAreaWB_mm2: 6.76; AEC Category: Q200; SizeArea_mm2: 2.56; CompType: IC; AEC Qualified: N; SizeZ_mm: 0.6

## Sheet DRV81325-QAD_IC.SchDoc
size 431 x 279 mm; Date: Not shown in title block; ApprovedBy: Not shown in title block; CheckedBy: Not shown in title block; Author: Not shown in title block; CompanyName: Not shown in title block; Engineer: Not shown in title block; Organization: Not shown in title block; Address1: Not shown in title block; Address2: Not shown in title block; Address3: Not shown in title block; Address4: Not shown in title block; DocumentNumber: 1; Revision: Use project parameter SCH_Rev; SheetNumber: 3; SheetTotal: 5; PageSetup: Record=PageOptions¦CenterHorizontal=True¦CenterVertical=True¦PrintScale=1.00¦XCorrection=1.00¦YCorrection=1.00¦PrintKind=0¦BorderSize=5000000¦LeftOffset=0¦BottomOffset=0¦Orientation=2¦PaperLength=1000¦PaperWidth=1000¦Scale=100¦PaperSource=15¦PrintQuality=600¦MediaType=1¦DitherType=10¦PaperKind=Letter¦PrintScaleMode=1
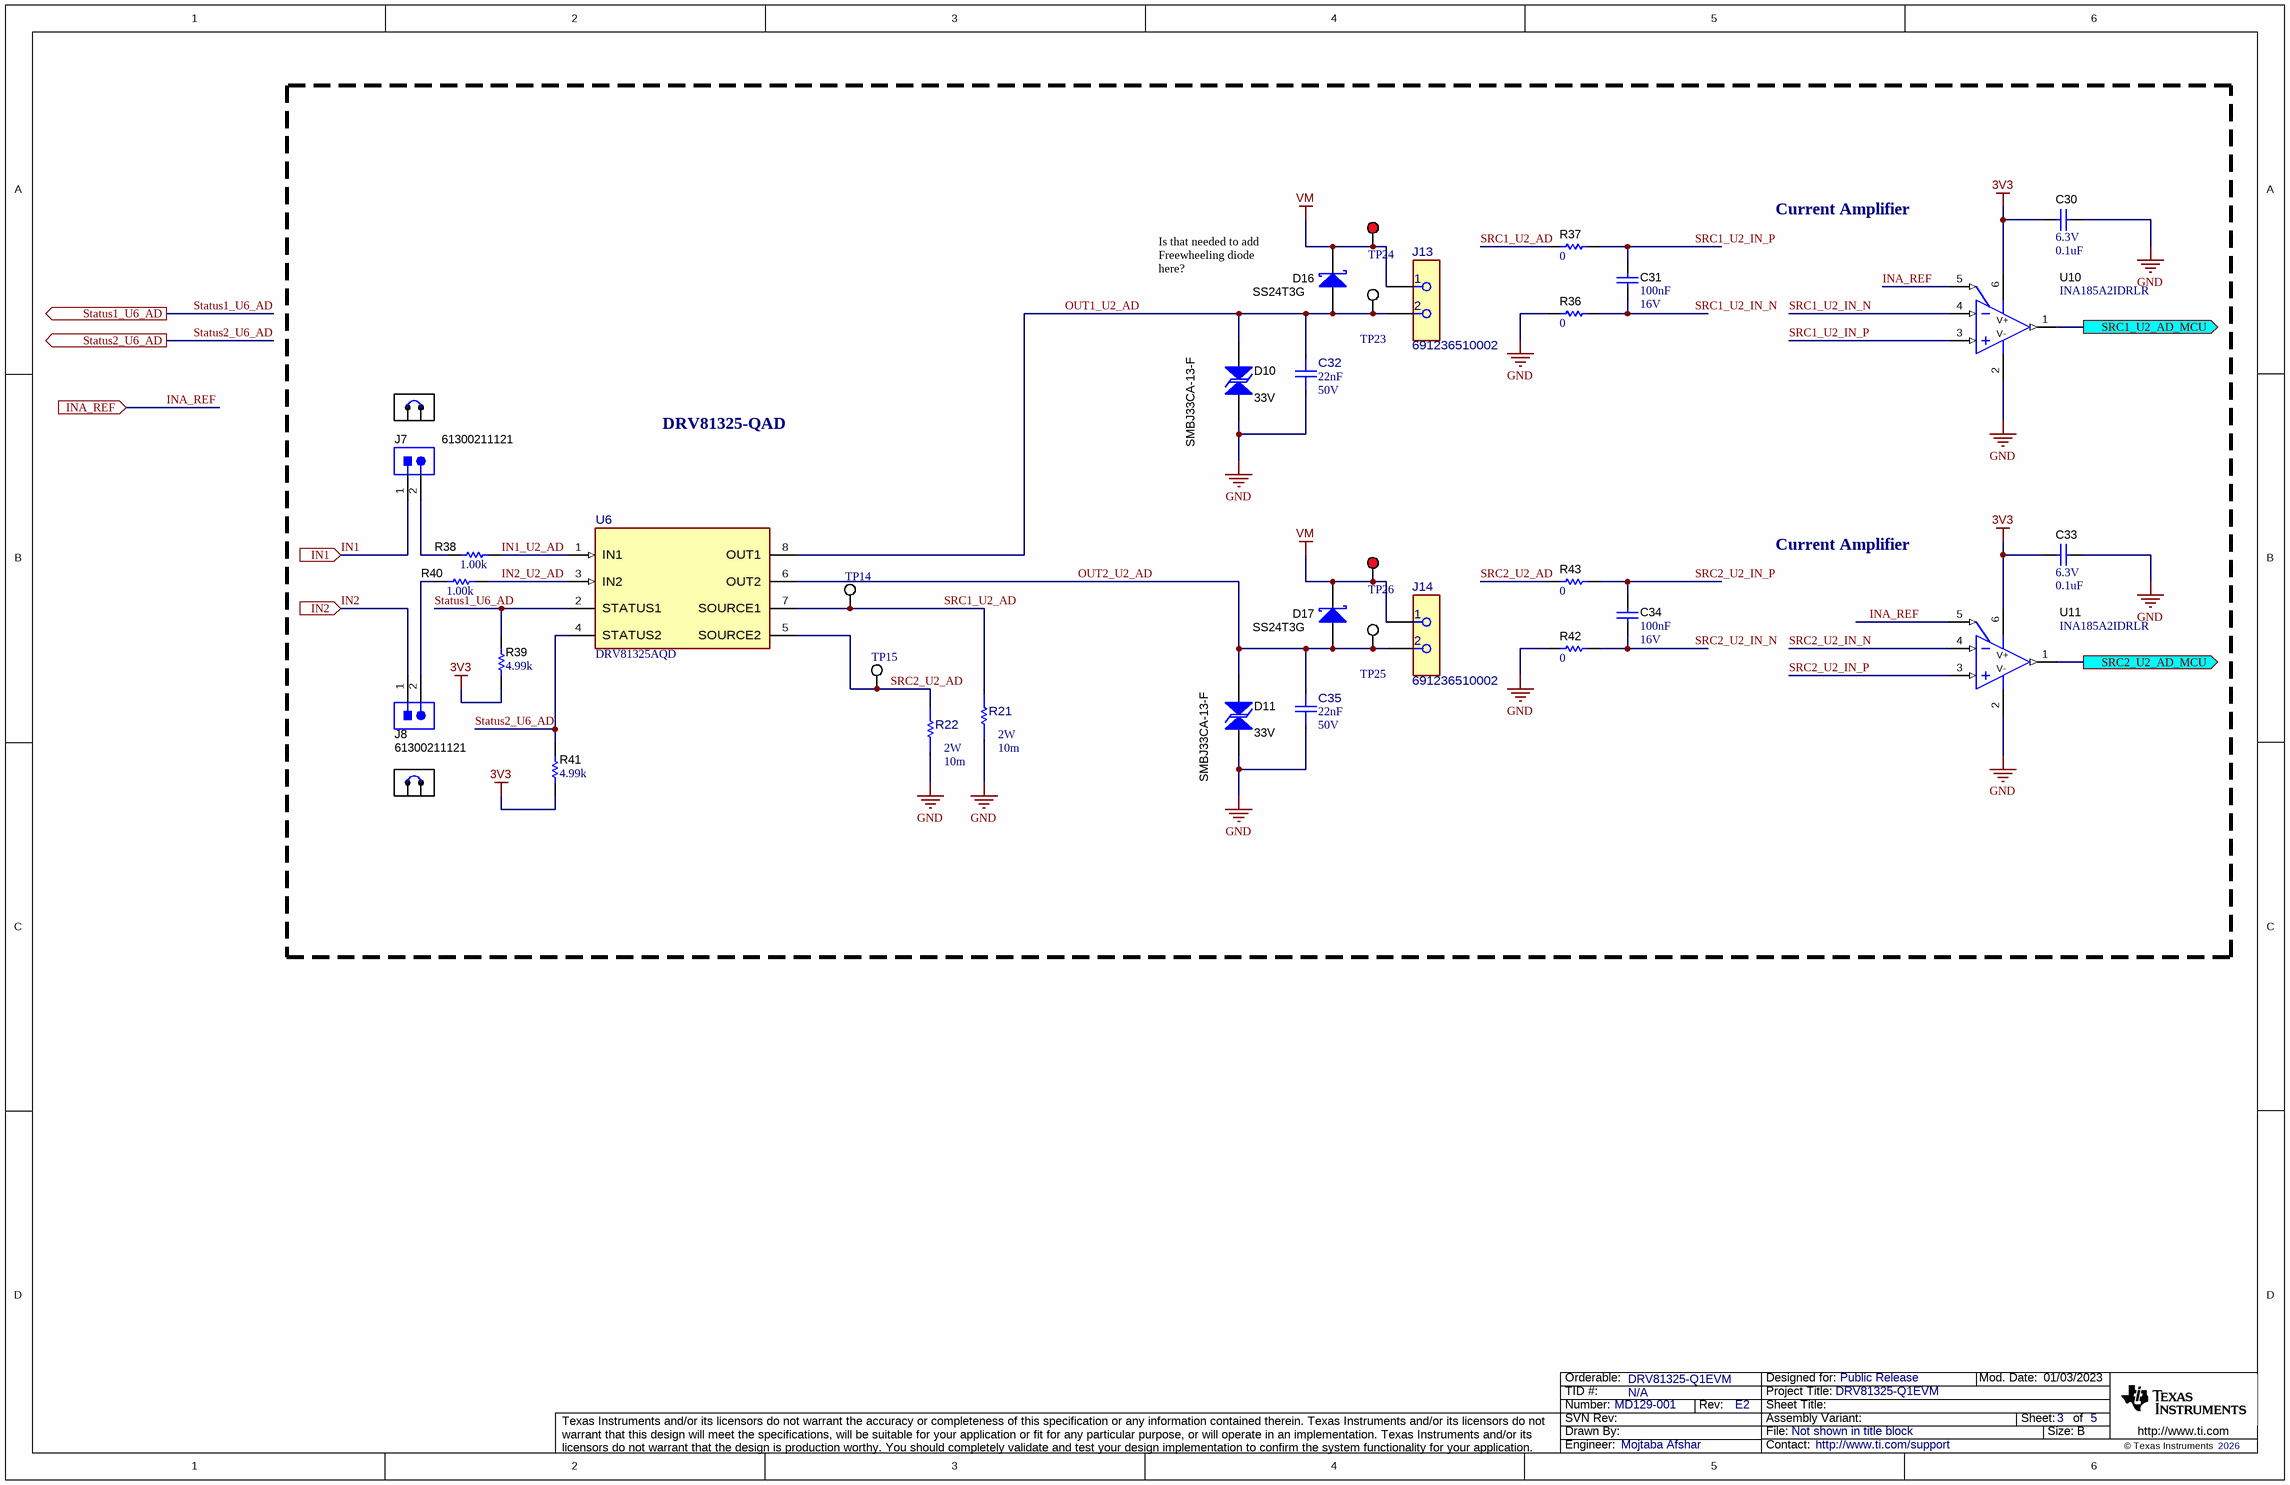
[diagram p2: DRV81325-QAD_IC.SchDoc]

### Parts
C30  VDC_V: 6.3V  ValueDisplayed: 0.1uF  [0402]  (hidden comment: 885012105001)
C31  Cap_F: 100nF  VDC_V: 16V  [0603]  (hidden comment: 885012206046)
C32  Cap_F: 22nF  VDC_V: 50V  [FP-885012206091_0603-MFG]  (hidden comment: 885012206091)
C33  VDC_V: 6.3V  ValueDisplayed: 0.1uF  [0402]  (hidden comment: 885012105001)
C34  Cap_F: 100nF  VDC_V: 16V  [0603]  (hidden comment: 885012206046)
C35  Cap_F: 22nF  VDC_V: 50V  [FP-885012206091_0603-MFG]  (hidden comment: 885012206091)
D10  SMBJ33CA-13-F  value 33V  [SMB-Bi]
D11  SMBJ33CA-13-F  value 33V  [SMB-Bi]
D16  SS24T3G  [SMB]
D17  SS24T3G  [SMB]
J7  61300211121  [WURTH_61300211121]
J8  61300211121  [WURTH_61300211121]
J13  691236510002  [FP-691236510002_HHR2-MFG]
J14  691236510002  [FP-691236510002_HHR2-MFG]
R21  Res_ohm: 10m  Power_W: 2W  [FP-PCS2512DR0100ET_2512-MFG]  (hidden comment: PCS2512DR0100ET)
R22  Res_ohm: 10m  Power_W: 2W  [FP-PCS2512DR0100ET_2512-MFG]  (hidden comment: PCS2512DR0100ET)
R36  ValueDisplayed: 0  [0603]  (hidden comment: ERJ-3GEY0R00V)
R37  ValueDisplayed: 0  [0603]  (hidden comment: ERJ-3GEY0R00V)
R38  ValueDisplayed: 1.00k  [0603]  (hidden comment: RC0603FR-071KL)
R39  ValueDisplayed: 4.99k  [0603]  (hidden comment: RC0603FR-074K99L)
R40  ValueDisplayed: 1.00k  [0603]  (hidden comment: RC0603FR-071KL)
R41  ValueDisplayed: 4.99k  [0603]  (hidden comment: RC0603FR-074K99L)
R42  ValueDisplayed: 0  [0603]  (hidden comment: ERJ-3GEY0R00V)
R43  ValueDisplayed: 0  [0603]  (hidden comment: ERJ-3GEY0R00V)
SH-J7  60900213421  [Wurth_60900213421]  (value not drawn)
SH-J8  60900213421  [Wurth_60900213421]  (value not drawn)
TP14  5002  [Keystone5002]  (value not drawn)
TP15  5002  [Keystone5002]  (value not drawn)
TP23  5012  [Keystone5012]  (value not drawn)
TP24  5010  [Keystone5010]  (value not drawn)
TP25  5012  [Keystone5012]  (value not drawn)
TP26  5010  [Keystone5010]  (value not drawn)
U6  DRV81325AQD  [D0008A-MFG]
U10  INA185A2IDRLR  [DRL0006A]
U11  INA185A2IDRLR  [DRL0006A]

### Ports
IN1 (in), IN2 (in), INA_REF (in), SRC1_U2_AD_MCU (out), SRC2_U2_AD_MCU (out), Status1_U6_AD (out), Status2_U6_AD (out)

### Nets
3V3: C30.2 C33.2 R39.1 R41.1 U10.6(V+) U11.6(V+)
GND: C30.1 C32.1 C33.1 C35.1 D10.1 D11.1 R21.1 R22.1 R36.1 R42.1 U10.2(V-) U11.2(V-)
VM: D16.1(K) D17.1(K) J13.1 J14.1 TP24.1 TP26.1
IN1: J7.1 ; port IN1
IN1_U2_AD: R38.2 U6.1(IN1)
IN2: J8.1 ; port IN2
IN2_U2_AD: R40.2 U6.3(IN2)
INA_REF: U10.5(REF) U11.5(REF) ; port INA_REF
OUT1_U2_AD: C32.2 D10.2 D16.2(A) J13.2 TP23.1 U6.8(OUT1)
OUT2_U2_AD: C35.2 D11.2 D17.2(A) J14.2 TP25.1 U6.6(OUT2)
SRC1_U2_AD: R21.2 R37.1 TP14.1 U6.7(SOURCE1)
SRC1_U2_AD_MCU: U10.1(OUT) ; port SRC1_U2_AD_MCU
SRC1_U2_IN_N: C31.2 R36.2 U10.4(IN-)
SRC1_U2_IN_P: C31.1 R37.2 U10.3(IN+)
SRC2_U2_AD: R22.2 R43.1 TP15.1 U6.5(SOURCE2)
SRC2_U2_AD_MCU: U11.1(OUT) ; port SRC2_U2_AD_MCU
SRC2_U2_IN_N: C34.2 R42.2 U11.4(IN-)
SRC2_U2_IN_P: C34.1 R43.2 U11.3(IN+)
Status1_U6_AD: R39.2 U6.2(STATUS1) ; port Status1_U6_AD
Status2_U6_AD: R41.2 U6.4(STATUS2) ; port Status2_U6_AD
NetJ7_2: J7.2 R38.1
NetJ8_2: J8.2 R40.1

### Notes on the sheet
- Current Amplifier
- Is that needed to add Freewheeling diode here?
- DRV81325-QAD

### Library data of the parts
C30 C33 = CMP-0006219-2: as C24 on sheet DRV81325-QD_IC
C31 C34 = CMP-0006829-4: as C25 on sheet DRV81325-QD_IC
C32 C35 = CMP-0120895-1: as C26 on sheet DRV81325-QD_IC
D10 D11 = CMP-0005564-3: as D8 on sheet DRV81325-QD_IC
D16 D17 = CMP-0028778-2: as D14 on sheet DRV81325-QD_IC
J7 J8 = CMP-0054794-2: as J5 on sheet DRV81325-QD_IC
J13 J14 = CMP-0121282-1: as J4 on sheet DRV81325-Q1_MCU_Supply
R21 R22 = CMP-0088493-1: as R19 on sheet DRV81325-QD_IC
R36 R37 R42 R43 = CMP-0025874-4: as R27 on sheet DRV81325-QD_IC
R38 R40 = CMP-0022895-5: as R13 on sheet DRV81325-Q1_MCU_Supply
R39 R41 = CMP-0023155-5: RES, 4.99 k, 1%, 0.1 W, 0603; Manufacturer: Yageo; Power_W: 100mW; TempCo: 100 ppm/C; Value_Code: 4k99; Value: 4.99k; EIA_Code: E96; SizeX_mm: 1.6; SizeY_mm: 0.8; SizeZ_mm: 1; Value2: 0.1W; SizeArea_mm2: 1.28; AEC Qualified: N; VDC_V: 75V; AEC Category: Q200; SizeAreaWB_mm2: 4.68
SH-J7 SH-J8 = CMP-0003761-2: as SH1-J2-1 on sheet DRV81325-Q1_MCU_Supply
TP14 TP15 = CMP-0055139-2: as TP1 on sheet DRV81325-Q1_MCU_Supply
TP23 TP25 = CMP-0055149-2: as TP3 on sheet DRV81325-Q1_MCU_Supply
TP24 TP26 = CMP-0055147-2: as TP20 on sheet DRV81325-QD_IC
U6 = CMP-0127803-1: Manufacturer: Texas Instruments; SizeZ_mm: 1.75mm; Standoff Height: 0.11mm
U10 U11 = CMP-0085242-1: as U8 on sheet DRV81325-QD_IC

## Sheet DRV81325-QADDA_IC.SchDoc
size 431 x 279 mm; Date: Not shown in title block; ApprovedBy: Not shown in title block; CheckedBy: Not shown in title block; Author: Not shown in title block; CompanyName: Not shown in title block; Engineer: Not shown in title block; Organization: Not shown in title block; Address1: Not shown in title block; Address2: Not shown in title block; Address3: Not shown in title block; Address4: Not shown in title block; DocumentNumber: 1; Revision: Use project parameter SCH_Rev; SheetNumber: 4; SheetTotal: 5; PageSetup: Record=PageOptions¦CenterHorizontal=True¦CenterVertical=True¦PrintScale=1.00¦XCorrection=1.00¦YCorrection=1.00¦PrintKind=0¦BorderSize=5000000¦LeftOffset=0¦BottomOffset=0¦Orientation=2¦PaperLength=1000¦PaperWidth=1000¦Scale=100¦PaperSource=15¦PrintQuality=600¦MediaType=1¦DitherType=10¦PaperKind=Letter¦PrintScaleMode=1
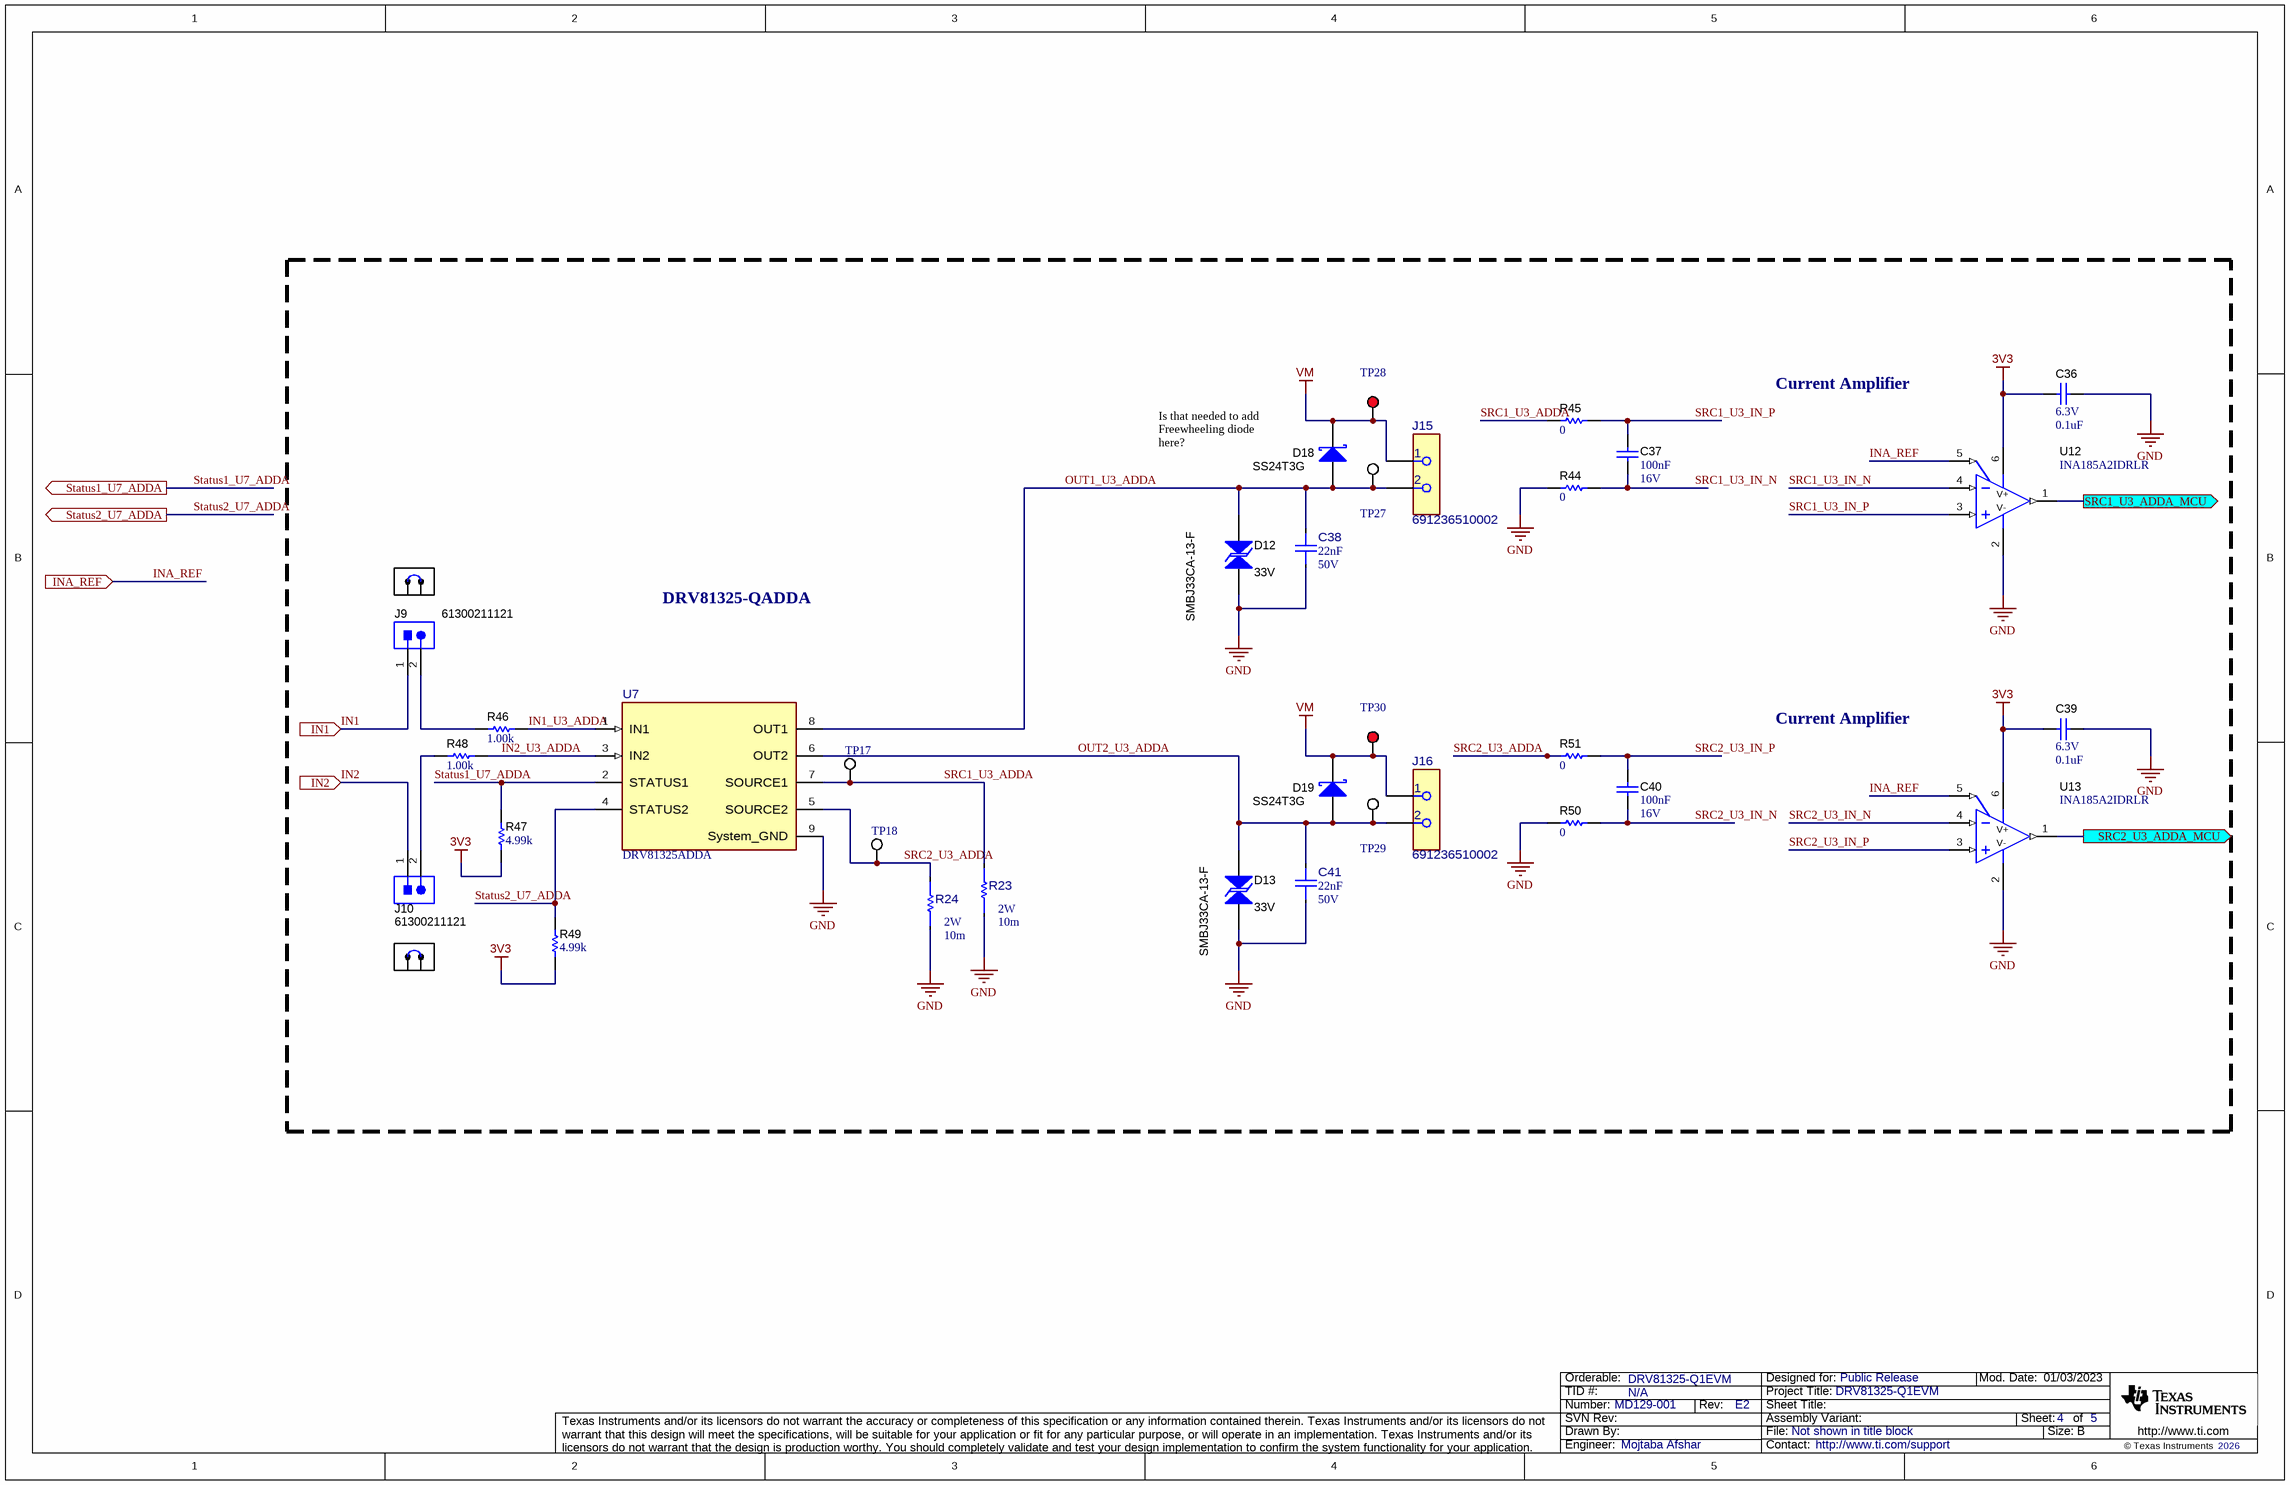
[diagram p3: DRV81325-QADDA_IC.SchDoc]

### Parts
C36  VDC_V: 6.3V  ValueDisplayed: 0.1uF  [0402]  (hidden comment: 885012105001)
C37  Cap_F: 100nF  VDC_V: 16V  [0603]  (hidden comment: 885012206046)
C38  Cap_F: 22nF  VDC_V: 50V  [FP-885012206091_0603-MFG]  (hidden comment: 885012206091)
C39  VDC_V: 6.3V  ValueDisplayed: 0.1uF  [0402]  (hidden comment: 885012105001)
C40  Cap_F: 100nF  VDC_V: 16V  [0603]  (hidden comment: 885012206046)
C41  Cap_F: 22nF  VDC_V: 50V  [FP-885012206091_0603-MFG]  (hidden comment: 885012206091)
D12  SMBJ33CA-13-F  value 33V  [SMB-Bi]
D13  SMBJ33CA-13-F  value 33V  [SMB-Bi]
D18  SS24T3G  [SMB]
D19  SS24T3G  [SMB]
J9  61300211121  [WURTH_61300211121]
J10  61300211121  [WURTH_61300211121]
J15  691236510002  [FP-691236510002_HHR2-MFG]
J16  691236510002  [FP-691236510002_HHR2-MFG]
R23  Res_ohm: 10m  Power_W: 2W  [FP-PCS2512DR0100ET_2512-MFG]  (hidden comment: PCS2512DR0100ET)
R24  Res_ohm: 10m  Power_W: 2W  [FP-PCS2512DR0100ET_2512-MFG]  (hidden comment: PCS2512DR0100ET)
R44  ValueDisplayed: 0  [0603]  (hidden comment: ERJ-3GEY0R00V)
R45  ValueDisplayed: 0  [0603]  (hidden comment: ERJ-3GEY0R00V)
R46  ValueDisplayed: 1.00k  [0603]  (hidden comment: RC0603FR-071KL)
R47  ValueDisplayed: 4.99k  [0603]  (hidden comment: RC0603FR-074K99L)
R48  ValueDisplayed: 1.00k  [0603]  (hidden comment: RC0603FR-071KL)
R49  ValueDisplayed: 4.99k  [0603]  (hidden comment: RC0603FR-074K99L)
R50  ValueDisplayed: 0  [0603]  (hidden comment: ERJ-3GEY0R00V)
R51  ValueDisplayed: 0  [0603]  (hidden comment: ERJ-3GEY0R00V)
SH-J9  60900213421  [Wurth_60900213421]  (value not drawn)
SH-J10  60900213421  [Wurth_60900213421]  (value not drawn)
TP17  5002  [Keystone5002]  (value not drawn)
TP18  5002  [Keystone5002]  (value not drawn)
TP27  5012  [Keystone5012]  (value not drawn)
TP28  5010  [Keystone5010]  (value not drawn)
TP29  5012  [Keystone5012]  (value not drawn)
TP30  5010  [Keystone5010]  (value not drawn)
U7  DRV81325ADDA  [DDA0008B-MFG]
U12  INA185A2IDRLR  [DRL0006A]
U13  INA185A2IDRLR  [DRL0006A]

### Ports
IN1 (in), IN2 (in), INA_REF (in), SRC1_U3_ADDA_MCU (out), SRC2_U3_ADDA_MCU (out), Status1_U7_ADDA (out), Status2_U7_ADDA (out)

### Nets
3V3: C36.2 C39.2 R47.1 R49.1 U12.6(V+) U13.6(V+)
GND: C36.1 C38.1 C39.1 C41.1 D12.1 D13.1 R23.1 R24.1 R44.1 R50.1 U7.9(System_GND) U12.2(V-) U13.2(V-)
VM: D18.1(K) D19.1(K) J15.1 J16.1 TP28.1 TP30.1
IN1: J9.1 ; port IN1
IN1_U3_ADDA: R46.2 U7.1(IN1)
IN2: J10.1 ; port IN2
IN2_U3_ADDA: R48.2 U7.3(IN2)
INA_REF: U12.5(REF) U13.5(REF) ; port INA_REF
OUT1_U3_ADDA: C38.2 D12.2 D18.2(A) J15.2 TP27.1 U7.8(OUT1)
OUT2_U3_ADDA: C41.2 D13.2 D19.2(A) J16.2 TP29.1 U7.6(OUT2)
SRC1_U3_ADDA: R23.2 R45.1 TP17.1 U7.7(SOURCE1)
SRC1_U3_ADDA_MCU: U12.1(OUT) ; port SRC1_U3_ADDA_MCU
SRC1_U3_IN_N: C37.2 R44.2 U12.4(IN-)
SRC1_U3_IN_P: C37.1 R45.2 U12.3(IN+)
SRC2_U3_ADDA: R24.2 R51.1 TP18.1 U7.5(SOURCE2)
SRC2_U3_ADDA_MCU: U13.1(OUT) ; port SRC2_U3_ADDA_MCU
SRC2_U3_IN_N: C40.2 R50.2 U13.4(IN-)
SRC2_U3_IN_P: C40.1 R51.2 U13.3(IN+)
Status1_U7_ADDA: R47.2 U7.2(STATUS1) ; port Status1_U7_ADDA
Status2_U7_ADDA: R49.2 U7.4(STATUS2) ; port Status2_U7_ADDA
NetJ9_2: J9.2 R46.1
NetJ10_2: J10.2 R48.1

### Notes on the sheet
- Current Amplifier
- Is that needed to add Freewheeling diode here?
- DRV81325-QADDA

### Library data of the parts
C36 C39 = CMP-0006219-2: as C24 on sheet DRV81325-QD_IC
C37 C40 = CMP-0006829-4: as C25 on sheet DRV81325-QD_IC
C38 C41 = CMP-0120895-1: as C26 on sheet DRV81325-QD_IC
D12 D13 = CMP-0005564-3: as D8 on sheet DRV81325-QD_IC
D18 D19 = CMP-0028778-2: as D14 on sheet DRV81325-QD_IC
J9 J10 = CMP-0054794-2: as J5 on sheet DRV81325-QD_IC
J15 J16 = CMP-0121282-1: as J4 on sheet DRV81325-Q1_MCU_Supply
R23 R24 = CMP-0088493-1: as R19 on sheet DRV81325-QD_IC
R44 R45 R50 R51 = CMP-0025874-4: as R27 on sheet DRV81325-QD_IC
R46 R48 = CMP-0022895-5: as R13 on sheet DRV81325-Q1_MCU_Supply
R47 R49 = CMP-0023155-5: as R39 on sheet DRV81325-QAD_IC
SH-J9 SH-J10 = CMP-0003761-2: as SH1-J2-1 on sheet DRV81325-Q1_MCU_Supply
TP17 TP18 = CMP-0055139-2: as TP1 on sheet DRV81325-Q1_MCU_Supply
TP27 TP29 = CMP-0055149-2: as TP3 on sheet DRV81325-Q1_MCU_Supply
TP28 TP30 = CMP-0055147-2: as TP20 on sheet DRV81325-QD_IC
U7 = CMP-0127624-1: Dual Channel Protected Low side switch, HSOIC8; Manufacturer: Texas Instruments; SizeZ_mm: 1.7mm; AEC Qualified: Yes; AEC Grade: Grade 1; Max Supply Voltage: 5.5V; Min Supply Voltage: 3V; Number Of Outputs: 2; Standoff Height: 0mm; TaMax_C: +125°C; TaMin_C: -40°C; TJmax_C: +150°C
U12 U13 = CMP-0085242-1: as U8 on sheet DRV81325-QD_IC

## Sheet DRV81325-Q1_HW.SchDoc: HARDWARE
size 431 x 279 mm; Date: Not shown in title block; ApprovedBy: Not shown in title block; CheckedBy: Not shown in title block; Author: Not shown in title block; CompanyName: Not shown in title block; DrawnBy: Mojtaba Afshar; Engineer: Not shown in title block; Organization: Not shown in title block; Address1: Not shown in title block; Address2: Not shown in title block; Address3: Not shown in title block; Address4: Not shown in title block; DocumentNumber: 1; Revision: Use project parameter SCH_Rev; SheetNumber: 5; SheetTotal: 5; PageSetup: Record=PageOptions¦CenterHorizontal=True¦CenterVertical=True¦PrintScale=1.00¦XCorrection=1.00¦YCorrection=1.00¦PrintKind=0¦BorderSize=5000000¦LeftOffset=0¦BottomOffset=0¦Orientation=2¦PaperLength=1000¦PaperWidth=1000¦Scale=100¦PaperSource=15¦PrintQuality=600¦MediaType=1¦DitherType=10¦PaperKind=Letter¦PrintScaleMode=1
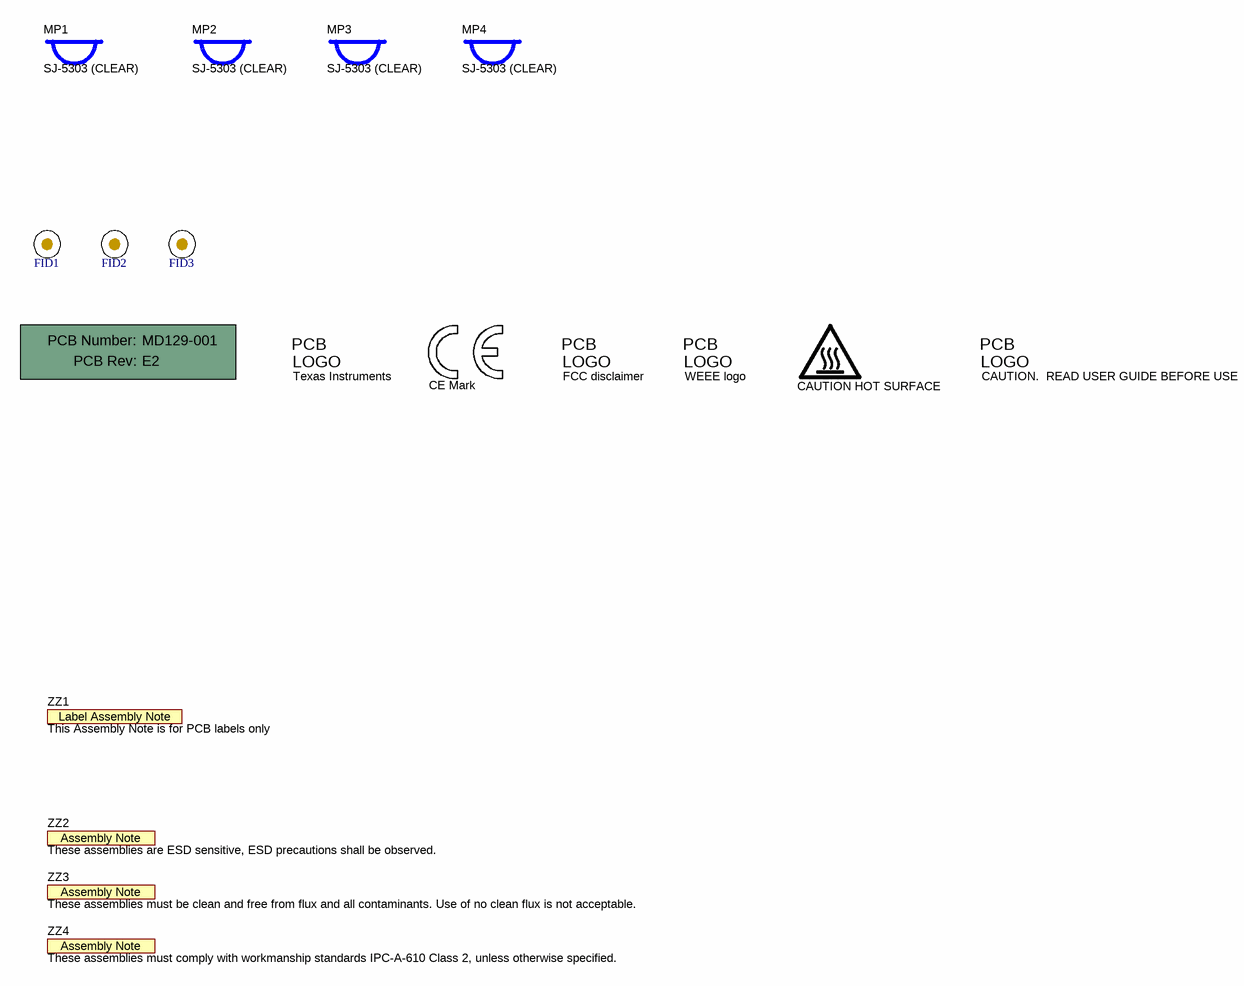
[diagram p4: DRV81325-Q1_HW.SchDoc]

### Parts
!PCB1  Printed Circuit Board  (value not drawn)  (mechanical)
FID1  Fiducial  [Fiducial10-20]  (value not drawn)
FID2  Fiducial  [Fiducial10-20]  (value not drawn)
FID3  Fiducial  [Fiducial10-20]  (value not drawn)
LOGO1  CAUTION HOT SURFACE  [IEC_HotSurface_Small]  (no BOM)
Logo2  CE Mark  [CE_Mark_5mm]  (no BOM)
Logo3  Texas Instruments  [TI_Stacked_Overlay_Small]  (no BOM)
Logo4  FCC disclaimer  [FCC_disclaimer]  (no BOM)
Logo5  WEEE logo  [WEEE_Minimum]  (no BOM)
Logo6  CAUTION.  READ USER GUIDE BEFORE USE  [IEC_Caution_Small]  (no BOM)
MP1  SJ-5303 (CLEAR)  [Bumpon_SJ5003Transparent]
MP2  SJ-5303 (CLEAR)  [Bumpon_SJ5003Transparent]
MP3  SJ-5303 (CLEAR)  [Bumpon_SJ5003Transparent]
MP4  SJ-5303 (CLEAR)  [Bumpon_SJ5003Transparent]
ZZ1  This Assembly Note is for PCB labels only  [AssemblyNoteLabel]  (no BOM)
ZZ2  These assemblies are ESD sensitive, ESD precautions shall be observed.  [AssemblyNote]  (no BOM)
ZZ3  These assemblies must be clean and free from flux and all contaminants. Use of no clean flux is not acceptable.  [AssemblyNote]  (no BOM)
ZZ4  These assemblies must comply with workmanship standards IPC-A-610 Class 2, unless otherwise specified.  [AssemblyNote]  (no BOM)

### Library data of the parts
!PCB1 = CMP-0003618-2: Manufacturer: Any; PartNumber: MD129-001
FID1-FID3 = CMP-0077181-1: Fiducial mark.  There is nothing to buy or mount.
LOGO1 = CMP-0074837-2: IEC 61010-1 Hot Surface Warning; Manufacturer: Texas Instruments; SymbolCreator: a0412235; CompType: IC; AEC Category: Q200
Logo2 = CMP-0074844-2: Manufacturer: Texas Instruments; SymbolCreator: a0412235; AEC Category: Q200; CompType: IC
Logo3 = CMP-0074838-1: Texas Instrument Corporate Signature; SymbolCreator: a0412235; Lib Reference: TI_Logo
Logo4 = CMP-0074847-1: FCC_disclaimer
Logo5 = CMP-0074769-4: Manufacturer: Texas Instruments; AEC Category: Q200; CompType: IC
Logo6 = CMP-0074836-1: IEC 61010-1 Caution Warning; SymbolCreator: a0412235; Lib Reference: IEC_Caution
MP1-MP4 = CMP-0003620-1: Bumpon, Hemisphere, 0.44 X 0.20, Clear; Manufacturer: 3M
ZZ1 = CMP-0003616-3
ZZ2 = CMP-0077236-1
ZZ3 = CMP-0077237-1
ZZ4 = CMP-0077238-1

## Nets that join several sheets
3V3: DRV81325-Q1_MCU_Supply (10 pins), DRV81325-QD_IC (5 pins), DRV81325-QAD_IC (6 pins), DRV81325-QADDA_IC (6 pins)
GND: DRV81325-Q1_MCU_Supply (49 pins), DRV81325-QD_IC (17 pins), DRV81325-QAD_IC (12 pins), DRV81325-QADDA_IC (13 pins)
VM: DRV81325-Q1_MCU_Supply (12 pins), DRV81325-QD_IC (6 pins), DRV81325-QAD_IC (6 pins), DRV81325-QADDA_IC (6 pins)
IN1: DRV81325-Q1_MCU_Supply (J2.4 TP3.1), DRV81325-QD_IC (J5.1), DRV81325-QAD_IC (J7.1), DRV81325-QADDA_IC (J9.1)
IN2: DRV81325-Q1_MCU_Supply (J2.6 TP4.1), DRV81325-QD_IC (J6.1), DRV81325-QAD_IC (J8.1), DRV81325-QADDA_IC (J10.1)
INA_REF: DRV81325-QD_IC (R25.1 R26.2 U8.5 U9.5), DRV81325-QAD_IC (U10.5 U11.5), DRV81325-QADDA_IC (U12.5 U13.5)
SRC1_U1_D_MCU: DRV81325-Q1_MCU_Supply (U1.26), DRV81325-QD_IC (U8.1)
SRC1_U2_AD_MCU: DRV81325-Q1_MCU_Supply (U1.31), DRV81325-QAD_IC (U10.1)
SRC1_U3_ADDA_MCU: DRV81325-Q1_MCU_Supply (U1.29), DRV81325-QADDA_IC (U12.1)
SRC2_U1_D_MCU: DRV81325-Q1_MCU_Supply (U1.25), DRV81325-QD_IC (U9.1)
SRC2_U2_AD_MCU: DRV81325-Q1_MCU_Supply (U1.30), DRV81325-QAD_IC (U11.1)
SRC2_U3_ADDA_MCU: DRV81325-Q1_MCU_Supply (U1.28), DRV81325-QADDA_IC (U13.1)
Status1_U6_AD: DRV81325-Q1_MCU_Supply (J2.8 R15.1 TP5.1), DRV81325-QAD_IC (R39.2 U6.2)
Status1_U7_ADDA: DRV81325-Q1_MCU_Supply (J2.12 R17.1 TP7.1), DRV81325-QADDA_IC (R47.2 U7.2)
Status2_U6_AD: DRV81325-Q1_MCU_Supply (J2.10 R16.1 TP6.1), DRV81325-QAD_IC (R41.2 U6.4)
Status2_U7_ADDA: DRV81325-Q1_MCU_Supply (J2.14 R18.1 TP8.1), DRV81325-QADDA_IC (R49.2 U7.4)

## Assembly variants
DRV81325-Q1EVM: not fitted C24 C25 C26 C27 C28 C29 C30 C31 C32 C33 C34 C35 C36 C37 C38 C39 C40 C41 D1 D8 D9 D10 D11 D12 D13 D14 D15 D16 D17 D18 D19 R5 R6 R11 R22 R23 R25 R26 R28 R32 R33 R36 R37 R42 R43 R46 R47 U2 U8 U9 U10 U11 U12 U13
